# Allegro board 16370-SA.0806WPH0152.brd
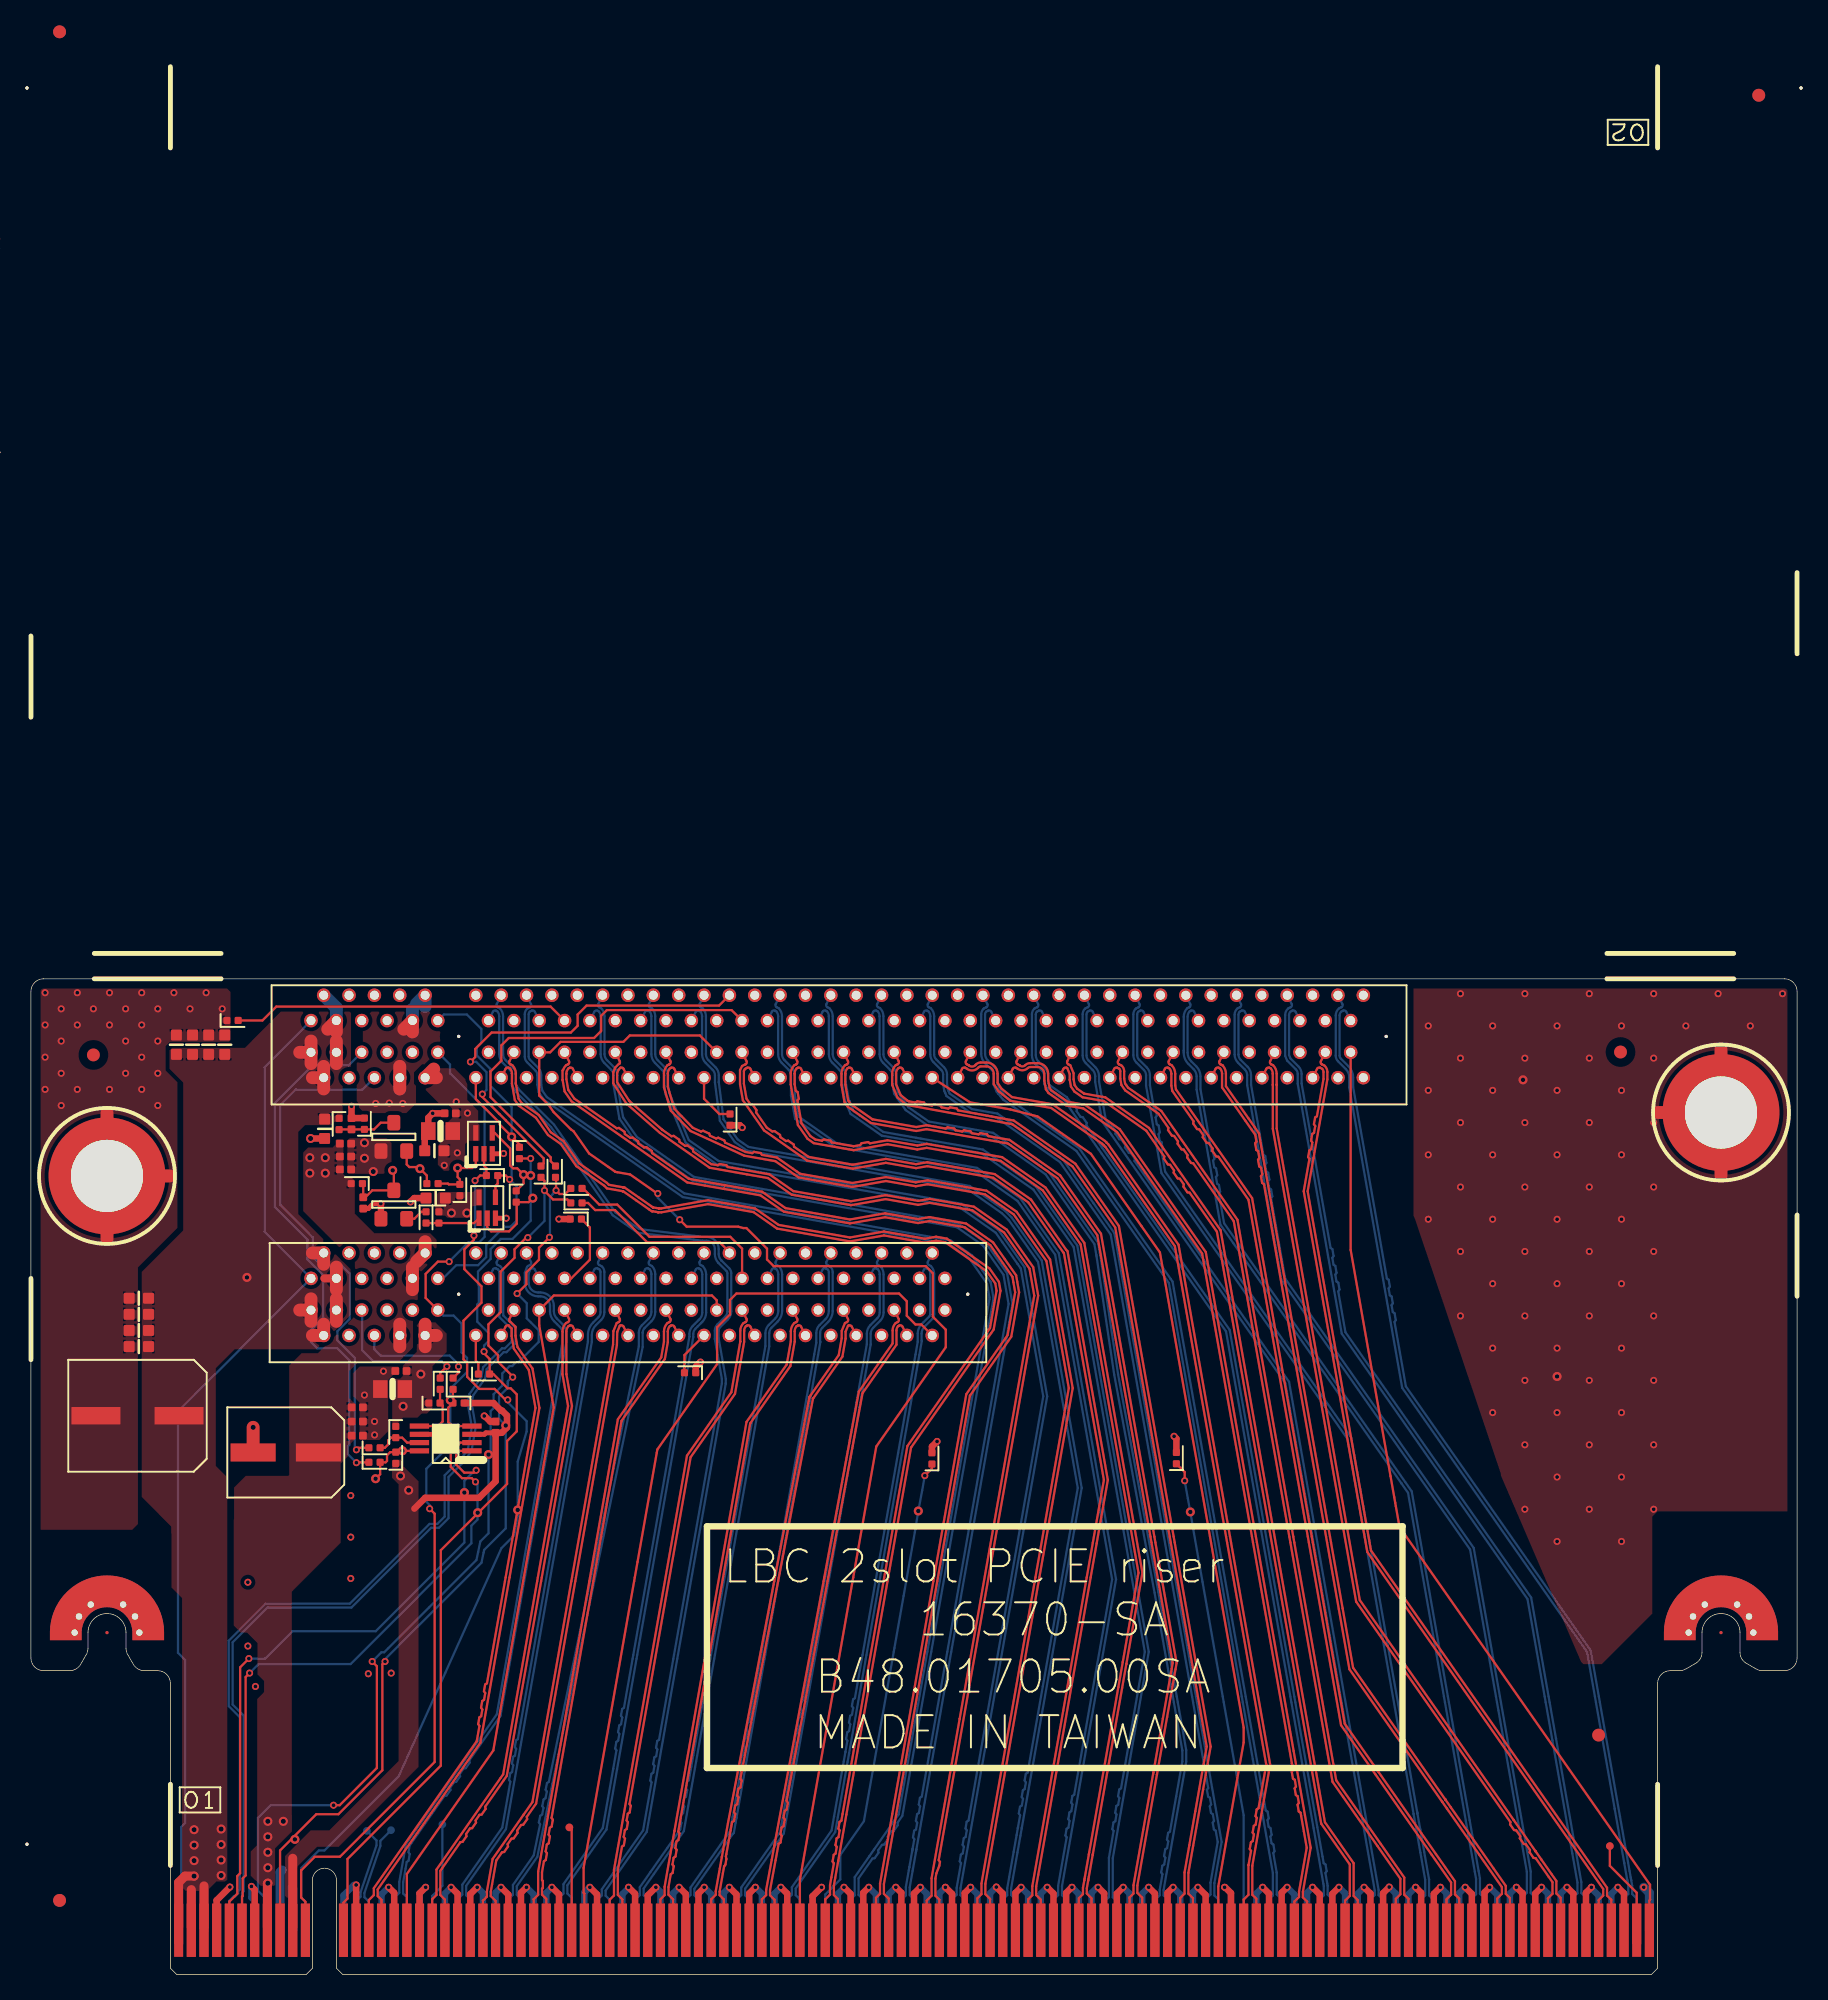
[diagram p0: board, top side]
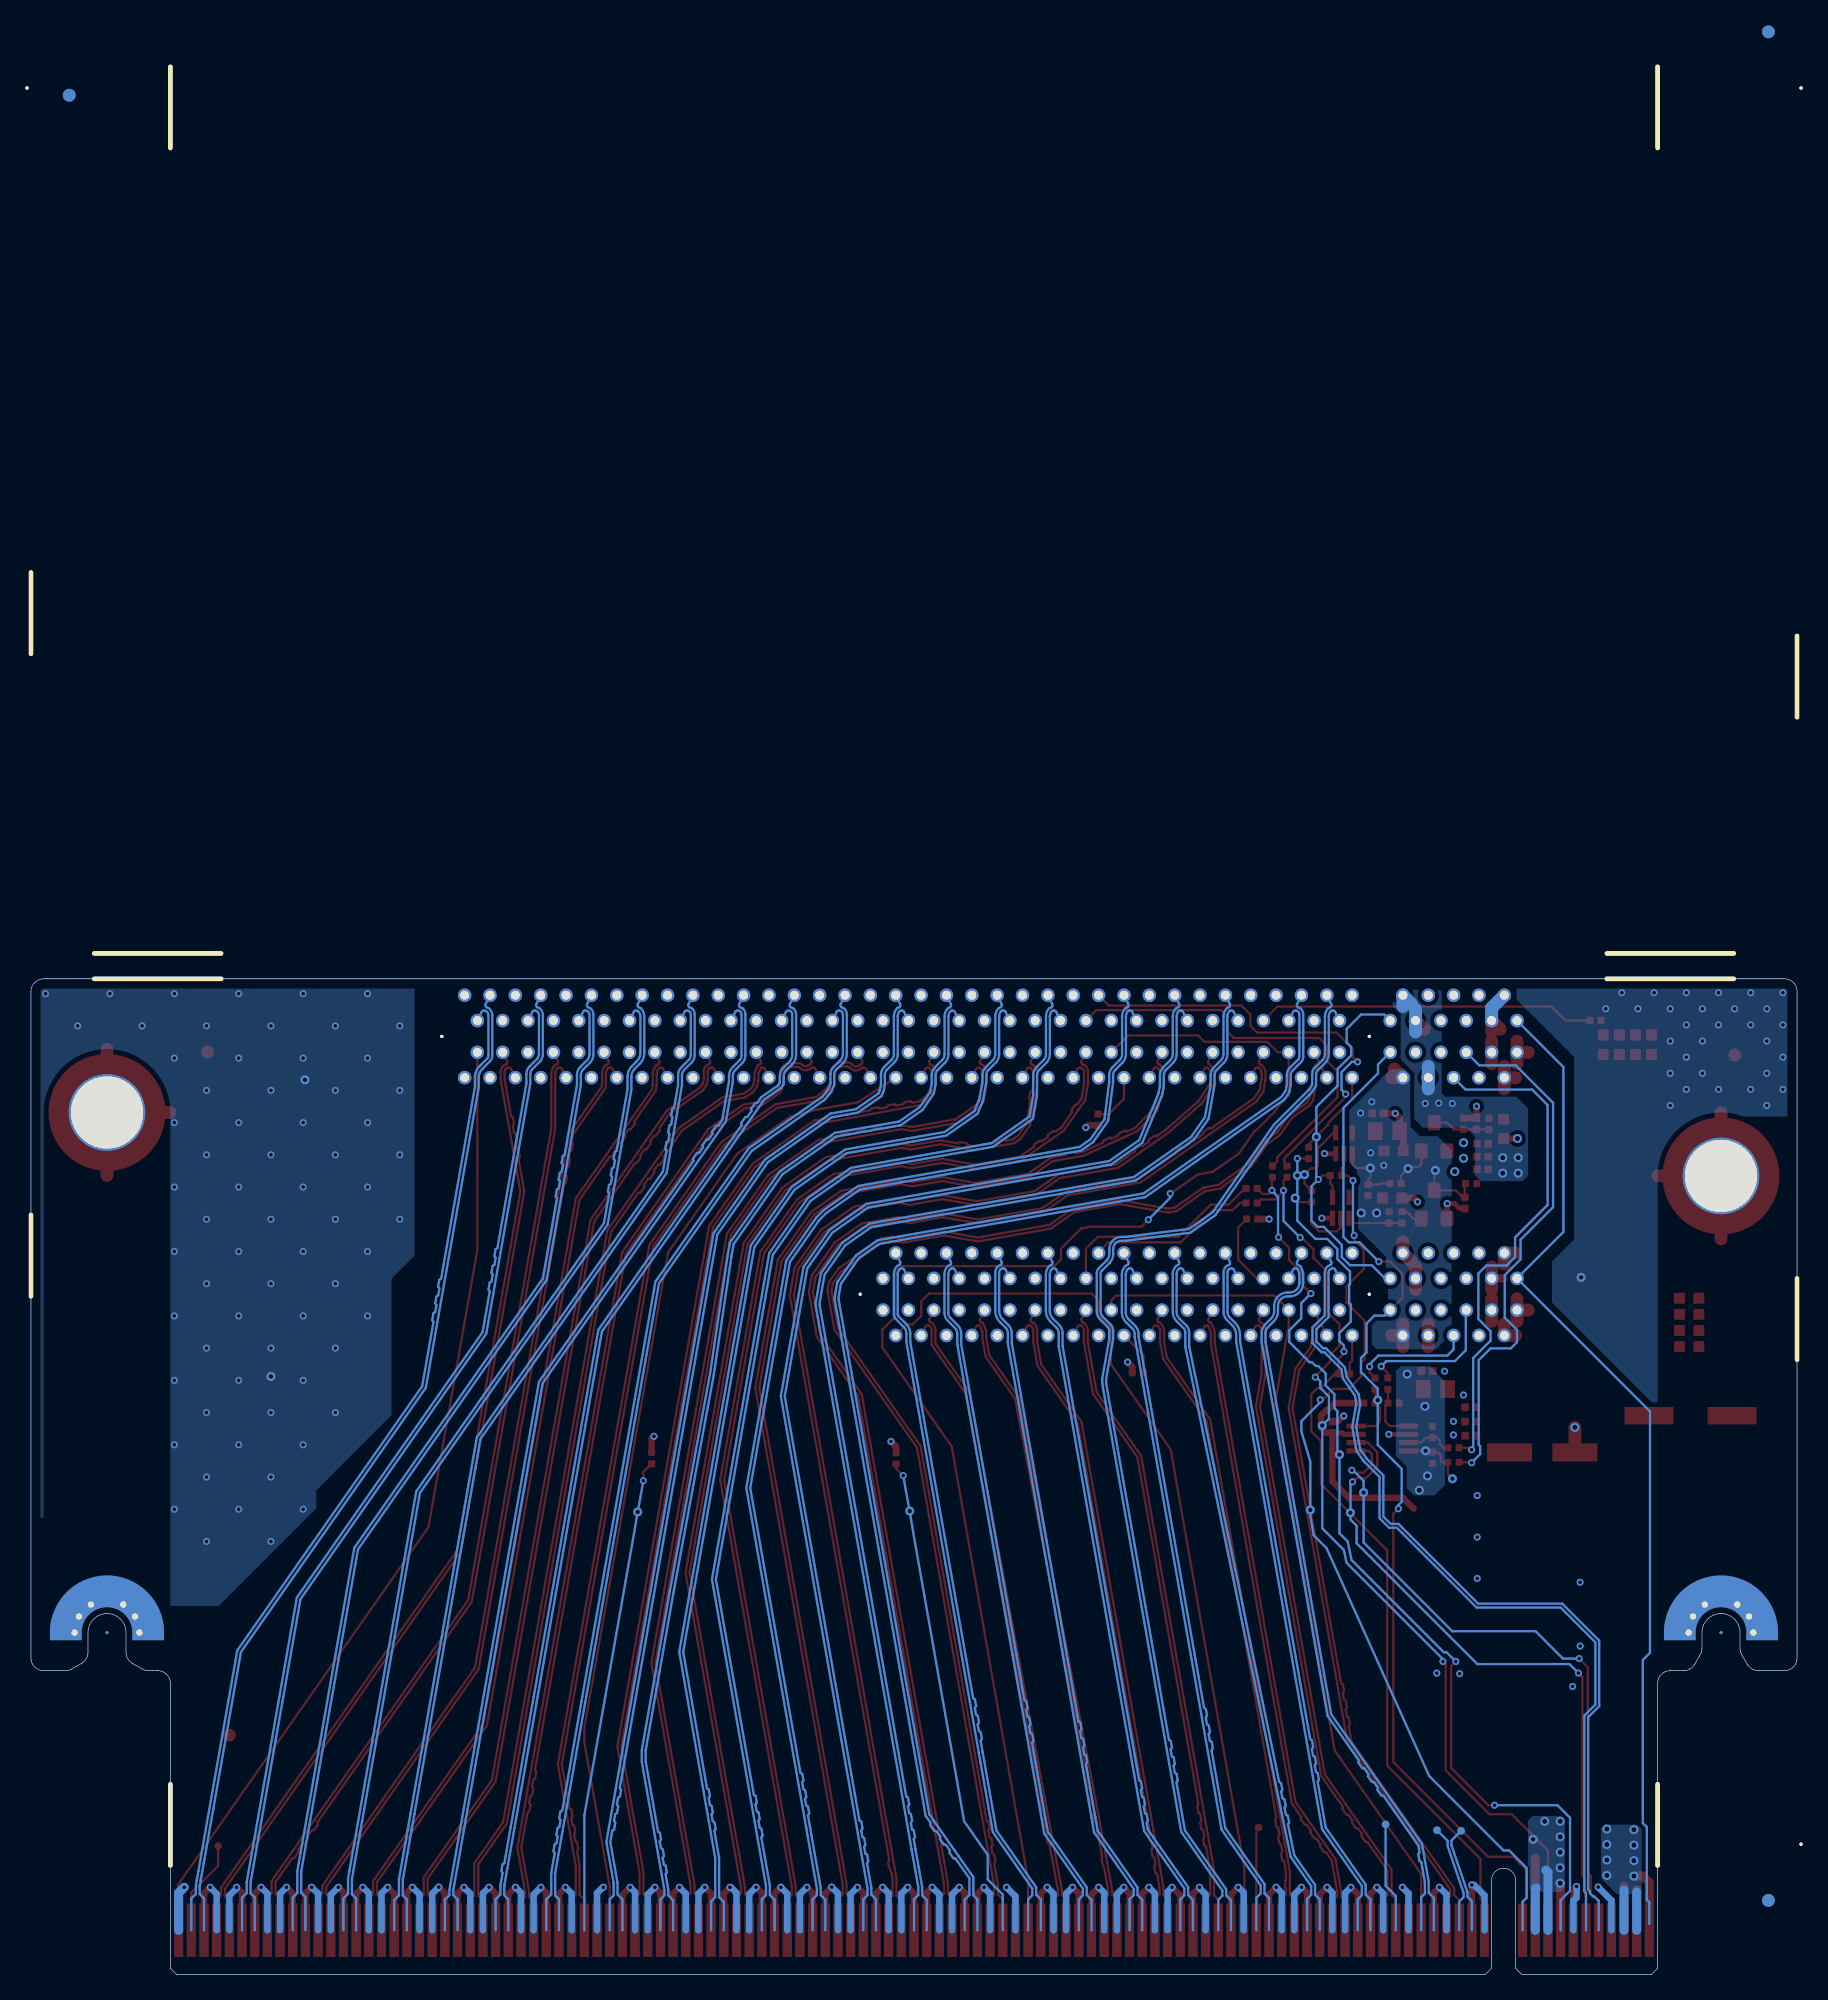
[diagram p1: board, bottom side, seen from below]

Outline 139.3 x 78.5 mm; copper layers: TOP, L2GND, L3GND, BOTTOM. Coordinates in mm from the lower left corner of the outline.
Outline path: 0,77.5 0,24.96 arc(0.29,24.25) 1,23.96 3.06,23.96 arc(3.56,24.09) 3.92,24.46 4.37,25.23 arc(4.47,25.47) 4.5,25.73 4.5,26.96 arc(6,28.46) 7.5,26.96 7.5,25.73 arc(7.53,25.47) 7.63,25.23 8.08,24.46 arc(8.44,24.09) 8.94,23.96 10,23.96 arc(10.71,23.67) 11,22.96 11,0.5 11.5,0 21.7,0 22.2,0.5 22.2,7.45 arc(23.15,8.4) 24.1,7.45 24.1,0.5 24.6,0 127.8,0 128.3,0.5 128.3,22.96 arc(128.59,23.67) 129.3,23.96 130.03,23.96 arc(130.29,23.99) 130.53,24.09 131.3,24.54 arc(131.67,24.9) 131.8,25.4 131.8,26.96 arc(133.3,28.46) 134.8,26.96 134.8,25.4 arc(134.93,24.9) 135.3,24.54 136.07,24.09 arc(136.31,23.99) 136.57,23.96 138.3,23.96 arc(139.01,24.25) 139.3,24.96 139.3,77.5 arc(139.01,78.21) 138.3,78.5 1,78.5 arc(0.29,78.21) 0,77.5 ; 3.2,62.96 arc(6,65.76) 8.8,62.96 arc(6,60.16) 3.2,62.96 ; 133.3,70.76 arc(136.1,67.96) 133.3,65.16 arc(130.5,67.96) 133.3,70.76

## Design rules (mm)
net group I2C: nets LAN_SMB_CLK LAN_SMB_DAT PCIE_SMCLK PCIE_SMCLK0 PCIE_SMCLK1 PCIE_SMDAT PCIE_SMDAT0 PCIE_SMDAT1 S0_PCIE_SMCLK S0_PCIE_SMDAT S0_SMB_CLK_A32 S0_SMB_DAT_A33 S1_PCIE_SMCLK S1_PCIE_SMDAT S1_SMB_CLK_A32 S1_SMB_DAT_A33
net group MISC: nets LAN_SMB_ALERT_N PCIE_CPRSNT_N PCIE_SLOT0_CPRSNT1_N PCIE_SLOT0_CPRSNT2_N PCIE_SLOT1_CPRSNT1_N PCIE_SLOT1_CPRSNT2_N PCIE_SLOT1_CPRSNT3_N PCIE_WAKE_N RSVD0 RSVD1 S0_SMB_ALERT_B12_N S1_SMB_ALERT_B12_N SLOT0_CONFIG SLOT0_ID_0 SLOT0_ID_1 SLOT1_CONFIG SLOT1_ID_0 SLOT1_ID_1
net group MISC_50_20_12: nets MB_PD_SLOT_PRSNT PCH_PLTRST_N PERST_N PERST_N_1 PERST_N_1_R PERST_O_1_R PERST_O_2_R RESET_IN RESET_O_1 RESET_O_2 RESET_P3V3_IN

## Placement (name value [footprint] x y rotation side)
C1  SCD1U25V3KX-GP  [C603H36]  11.48 73.31 180 top
C2  SCD1U25V3KX-GP  [C603H36]  12.75 73.31 180 top
C3  SCD1U25V3KX-GP  [C603H36]  14.02 73.31 180 top
C4  SCD1U25V3KX-GP  [C603H36]  15.29 73.31 180 top
C5  SCD1U16V2KX-3GP  [C402H22]  25.74 42.48 90 top
C6  SCD1U16V2KX-3GP  [C402H22]  25.74 43.6 90 top
C7  SCD1U16V2KX-3GP  [C402H22]  25.74 44.72 90 top
C8  SC10U6D3V5KX-4GP  [C805H58]  28.52 46.16 270 top
C9  SCD1U16V2KX-3GP  [C402H22]  29.18 47.58 270 top
C10  SCD1U25V3KX-GP  [C603H36]  8.51 53.32 270 top
C11  SCD1U25V3KX-GP  [C603H36]  8.51 52.05 270 top
C12  SCD1U25V3KX-GP  [C603H36]  8.51 50.78 270 top
C13  SCD1U25V3KX-GP  [C603H36]  8.51 49.51 270 top
C14  SCD1U16V2KX-3GP  [C402H22]  24.81 63.47 90 top
C15  SCD1U16V2KX-3GP  [C402H22]  24.81 64.49 90 top
C16  SCD1U16V2KX-3GP  [C402H22]  24.81 65.51 90 top
C17  SC10U6D3V5KX-4GP  [C805H58]  32.31 66.5 270 top
C18  SCD1U16V2KX-3GP  [C402H22]  33.07 67.89 270 top
C19  SCD01U16V2KX-3GP  [C402H22]  25.28 67.07 180 top
C20  SCD1U25V3KX-GP  [C603H36]  31.82 64.95 270 top
C21  SCD1U25V3KX-GP  [C603H36]  23.16 66.67 0 top
C22  SCD1U25V3KX-GP  [C603H36]  31.92 61.21 270 top
C23  SCD01U16V2KX-3GP  [C402H22]  26.21 60.83 0 top
C24  SCD1U16V2KX-3GP  [C402H22]  36.65 43.15 0 top
CN1  PCISLT98-79-GP  [G630H9811210TEU]  33.74 53.64 0 top
CN2  PCISLT164-33-GP  [2EG08227-D2W-DF]  33.74 73.96 0 top
GF1  GF-PCIE-230P-GP  [GF-PCIE-230P]  23.15 1.4 0 top
H1  STFT363B238R224H453-GP  [STFT363B238R224H453]  133.3 67.96 180 top
H2  STFT363B238R224H453-GP  [STFT363B238R224H453]  6 62.96 180 top
H3  GEN276X162R197X296-6-F-A-GP  [GEN276X162R197X296-6-F-A]  6 26.96 0 top
H4  GEN276X162R197X296-6-F-A-GP  [GEN276X162R197X296-6-F-A]  133.3 26.96 0 top
NOREF  -  []  -42 -27.95 0 top
NOREF#2  -  []  0 23.96 0 top
NOREF#3  *  [unnamed#2]  2.26 5.85 0 top
NOREF#4  -  [unnamed#2]  -0.31 10.28 0 top
NOREF#5  *  [unnamed#2]  136.28 148.15 0 top
NOREF#6  -  []  13.34 13.77 0 top
NOREF#7  *  [unnamed#2]  125.37 72.73 0 top
NOREF#8  -  [unnamed#2]  139.61 148.72 0 top
NOREF#9  -  []  -4 150.53 0 top
NOREF#10  -  []  0 23.96 0 top
NOREF#11  *  [unnamed#2]  4.93 72.5 0 top
NOREF#12  -  []  125.96 145.23 180 top
NOREF#13  -  []  0 23.96 0 top
NOREF#14  -  [unnamed#2]  -0.31 148.72 0 top
NOREF#15  *  [unnamed#2]  123.65 18.88 0 top
NOREF#16  *  [unnamed#2]  2.26 153.15 0 top
NOREF#17  *  [unnamed#2]  2.26 5.85 180 bottom
NOREF#18  *  [unnamed#2]  2.26 153.15 180 bottom
NOREF#19  *  [unnamed#2]  136.28 148.15 180 bottom
R1  8K2R2J-3-GP  [R402H16]  24.3 67.05 0 top
R2  3K3R2F-2-GP  [R402H16]  26.3 67.07 180 top
R3  0R2J-2-GP  [R402H16]  31.67 62.36 90 top
R4  0R2J-2-GP  [R402H16]  31.16 59.69 0 top
R5  0R2J-2-GP  [R402H16]  25.7 62.36 270 top
R6  0R2J-2-GP  [R402H16]  38.27 61.34 0 top
R7  100R2J-L-GP  [R402H15]  42.97 59.56 270 top
R8  100R2J-L-GP  [R402H15]  51.99 47.45 270 top
R9  100R2J-L-GP  [R402H15]  15.9 75.22 90 top
R10  100R2J-L-GP  [R402H15]  55.14 67.4 180 top
R13  4K7R2J-2-GP  [R402H16]  33.73 45.06 270 top
R14  4K7R2J-2-GP  [R402H16]  31.82 45.06 90 top
R15  4K7R2J-2-GP  [R402H16]  28.78 42.77 0 top
R16  4K7R2J-2-GP  [R402H16]  28.78 40.74 180 top
R17  4K7R2J-2-GP  [R402H16]  33.83 61.85 180 top
R19  0R2J-2-GP  [R402H16]  36.37 62.99 270 top
R20  4K7R2J-2-GP  [R402H16]  32.18 59.69 0 top
R33  1KR2J-1-GP  [R402H16]  71.07 40.69 180 top
R35  1KR2J-1-GP  [R402H16]  90.34 40.71 180 top
RE1  0R2J-2-GP  [R402H16]  32.28 46.58 0 top
RE2  0R2J-2-GP  [R402H16]  43.02 60.83 90 top
RE3  0R2J-2-GP  [R402H16]  43.02 61.97 90 top
RE4  0R2J-2-GP  [R402H16]  35.73 47.34 90 top
RE5  0R2J-2-GP  [R402H16]  40.23 63.3 180 top
RE6  0R2J-2-GP  [R402H16]  41.37 63.3 180 top
RE7  0R2J-2-GP  [R402H16]  33.3 46.58 0 top
RE8  0R2J-2-GP  [R402H16]  38.53 64.77 0 top
RE9  0R2J-2-GP  [R402H16]  27.1 41.53 90 top
RE10  0R2J-2-GP  [R402H16]  27.1 40.38 90 top
TC3  SE270U16VM-2-GP  [SE391427H276]  8.4 44.06 270 top
TC4  SE220U6D3VM-8GP  [SE331721H237]  20.1 41.16 270 top
TP1  -  [TPAD24]  26.5 11.33 180 bottom
TP2  -  [TPAD24]  28.4 11.39 180 bottom
TP3  -  [TPAD24]  124.53 10.13 0 top
TP6  -  [TPAD24]  42.47 11.61 0 top
TP7  -  [TPAD24]  32.45 11.84 180 bottom
U1  TPS3809K33-2-GP  [SOT-23-1H58]  28.62 66.04 0 top
U2  TPS3809K33-2-GP  [SOT-23-1H58]  28.62 60.7 0 top
U8  SNLVC1G08DCKRG4-GP  [SC70-5H44]  35.73 65.53 180 top
U9  SNLVC1G08DCKRG4-GP  [SC70-5H44]  35.99 60.45 180 top
U10  PCA9540BDP-T-GP  [SSOIC8-2H44]  32.71 42.26 90 top

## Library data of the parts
C1-C4 C10-C13 C20-C22 = C603H36: tolerance: 78.10422.2BL
C5-C7 C9 C14-C16 C18 C24 = C402H22: tolerance: 78.10421.2FL
C8 C17 = C805H58: tolerance: 78.10620.21L
C19 C23 = C402H22: tolerance: 78.10321.2FL
CN1 = G630H9811210TEU: tolerance: 020.50107.0098
CN2 = 2EG08227-D2W-DF: tolerance: 20.50449.164
GF1 = GF-PCIE-230P: tolerance: ZZ.GF001.711; alternate symbols: (TOP:GF-PCIE-230P)
H1 H2 = STFT363B238R224H453: tolerance: 086.2AT24.04R6
H3 H4 = GEN276X162R197X296-6-F-A: tolerance: ZZ.SCREW.511
R1 = R402H16: tolerance: 63.82234.1DL
R2 = R402H16: tolerance: 64.33015.6DL
R3-R6 R19 RE1-RE10 = R402H16: tolerance: 63.R0034.1DL
R7-R10 = R402H15: tolerance: 63.10134.L0L
R13-R17 R20 = R402H16: tolerance: 63.47234.1DL
R33 R35 = R402H16: tolerance: 63.10234.1DL
TC3 = SE391427H276: tolerance: 77.52771.01L
TC4 = SE331721H237: tolerance: 79.22710.E0L
TP1-TP3 TP6 TP7 = TPAD24: tolerance: ZZ.PAD24.001
U1 U2 = SOT-23-1H58: tolerance: 74.03809.07B
U8 U9 = SC70-5H44: tolerance: 73.01G08.DHG
U10 = SSOIC8-2H44: tolerance: 71.09540.A0W

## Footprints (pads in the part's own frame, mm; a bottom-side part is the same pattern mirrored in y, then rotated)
2EG08227-D2W-DF
  round 0.254 hole 2.362 unplated: (0,0) (73.15,0)
  round 1.067 hole 0.711: A1(-11.65,1.25) A2(-10.65,3.25) A3(-9.65,1.25) A4(-8.65,3.25) A5(-7.65,1.25) A6(-6.65,3.25) A7(-5.65,1.25) A8(-4.65,3.25) A9(-3.65,1.25) A10(-2.65,3.25) A11(-1.65,1.25) A12(1.35,3.25) A13(2.35,1.25) A14(3.35,3.25) A15(4.35,1.25) A16(5.35,3.25) A17(6.35,1.25) A18(7.35,3.25) A19(8.35,1.25) A20(9.35,3.25) A21(10.35,1.25) A22(11.35,3.25) A23(12.35,1.25) A24(13.35,3.25) A25(14.35,1.25) A26(15.35,3.25) A27(16.35,1.25) A28(17.35,3.25) A29(18.35,1.25) A30(19.35,3.25) A31(20.35,1.25) A32(21.35,3.25) A33(22.35,1.25) A34(23.35,3.25) A35(24.35,1.25) A36(25.35,3.25) A37(26.35,1.25) A38(27.35,3.25) A39(28.35,1.25) A40(29.35,3.25) A41(30.35,1.25) A42(31.35,3.25) A43(32.35,1.25) A44(33.35,3.25) A45(34.35,1.25) A46(35.35,3.25) A47(36.35,1.25) A48(37.35,3.25) A49(38.35,1.25) A50(39.35,3.25) A51(40.35,1.25) A52(41.35,3.25) A53(42.35,1.25) A54(43.35,3.25) A55(44.35,1.25) A56(45.35,3.25) A57(46.35,1.25) A58(47.35,3.25) A59(48.35,1.25) A60(49.35,3.25) A61(50.35,1.25) A62(51.35,3.25) A63(52.35,1.25) A64(53.35,3.25) A65(54.35,1.25) A66(55.35,3.25) A67(56.35,1.25) A68(57.35,3.25) A69(58.35,1.25) A70(59.35,3.25) A71(60.35,1.25) A72(61.35,3.25) A73(62.35,1.25) A74(63.35,3.25) A75(64.35,1.25) A76(65.35,3.25) A77(66.35,1.25) A78(67.35,3.25) A79(68.35,1.25) A80(69.35,3.25) A81(70.35,1.25) A82(71.35,3.25) B1(-11.65,-1.25) B2(-10.65,-3.25) B3(-9.65,-1.25) B4(-8.65,-3.25) B5(-7.65,-1.25) B6(-6.65,-3.25) B7(-5.65,-1.25) B8(-4.65,-3.25) B9(-3.65,-1.25) B10(-2.65,-3.25) B11(-1.65,-1.25) B12(1.35,-3.25) B13(2.35,-1.25) B14(3.35,-3.25) B15(4.35,-1.25) B16(5.35,-3.25) B17(6.35,-1.25) B18(7.35,-3.25) B19(8.35,-1.25) B20(9.35,-3.25) B21(10.35,-1.25) B22(11.35,-3.25) B23(12.35,-1.25) B24(13.35,-3.25) B25(14.35,-1.25) B26(15.35,-3.25) B27(16.35,-1.25) B28(17.35,-3.25) B29(18.35,-1.25) B30(19.35,-3.25) B31(20.35,-1.25) B32(21.35,-3.25) B33(22.35,-1.25) B34(23.35,-3.25) B35(24.35,-1.25) B36(25.35,-3.25) B37(26.35,-1.25) B38(27.35,-3.25) B39(28.35,-1.25) B40(29.35,-3.25) B41(30.35,-1.25) B42(31.35,-3.25) B43(32.35,-1.25) B44(33.35,-3.25) B45(34.35,-1.25) B46(35.35,-3.25) B47(36.35,-1.25) B48(37.35,-3.25) B49(38.35,-1.25) B50(39.35,-3.25) B51(40.35,-1.25) B52(41.35,-3.25) B53(42.35,-1.25) B54(43.35,-3.25) B55(44.35,-1.25) B56(45.35,-3.25) B57(46.35,-1.25) B58(47.35,-3.25) B59(48.35,-1.25) B60(49.35,-3.25) B61(50.35,-1.25) B62(51.35,-3.25) B63(52.35,-1.25) B64(53.35,-3.25) B65(54.35,-1.25) B66(55.35,-3.25) B67(56.35,-1.25) B68(57.35,-3.25) B69(58.35,-1.25) B70(59.35,-3.25) B71(60.35,-1.25) B72(61.35,-3.25) B73(62.35,-1.25) B74(63.35,-3.25) B75(64.35,-1.25) B76(65.35,-3.25) B77(66.35,-1.25) B78(67.35,-3.25) B79(68.35,-1.25) B80(69.35,-3.25) B81(70.35,-1.25) B82(71.35,-3.25)
C402H22
  custom 0.152x0.152 smd: 1(0,0.445) 2(0,-0.445)
C603H36
  custom 0.216x0.216 smd: 1(0,0.762) 2(0,-0.762)
C805H58
  rect 1.397x1.143 smd: 1(0,0.965) 2(0,-0.965)
G630H9811210TEU
  round 0.254 hole 2.362 unplated: (0,0) (40.15,0)
  round 1.067 hole 0.711: A1(-11.65,1.25) A2(-10.65,3.25) A3(-9.65,1.25) A4(-8.65,3.25) A5(-7.65,1.25) A6(-6.65,3.25) A7(-5.65,1.25) A8(-4.65,3.25) A9(-3.65,1.25) A10(-2.65,3.25) A11(-1.65,1.25) A12(1.35,3.25) A13(2.35,1.25) A14(3.35,3.25) A15(4.35,1.25) A16(5.35,3.25) A17(6.35,1.25) A18(7.35,3.25) A19(8.35,1.25) A20(9.35,3.25) A21(10.35,1.25) A22(11.35,3.25) A23(12.35,1.25) A24(13.35,3.25) A25(14.35,1.25) A26(15.35,3.25) A27(16.35,1.25) A28(17.35,3.25) A29(18.35,1.25) A30(19.35,3.25) A31(20.35,1.25) A32(21.35,3.25) A33(22.35,1.25) A34(23.35,3.25) A35(24.35,1.25) A36(25.35,3.25) A37(26.35,1.25) A38(27.35,3.25) A39(28.35,1.25) A40(29.35,3.25) A41(30.35,1.25) A42(31.35,3.25) A43(32.35,1.25) A44(33.35,3.25) A45(34.35,1.25) A46(35.35,3.25) A47(36.35,1.25) A48(37.35,3.25) A49(38.35,1.25) B1(-11.65,-1.25) B2(-10.65,-3.25) B3(-9.65,-1.25) B4(-8.65,-3.25) B5(-7.65,-1.25) B6(-6.65,-3.25) B7(-5.65,-1.25) B8(-4.65,-3.25) B9(-3.65,-1.25) B10(-2.65,-3.25) B11(-1.65,-1.25) B12(1.35,-3.25) B13(2.35,-1.25) B14(3.35,-3.25) B15(4.35,-1.25) B16(5.35,-3.25) B17(6.35,-1.25) B18(7.35,-3.25) B19(8.35,-1.25) B20(9.35,-3.25) B21(10.35,-1.25) B22(11.35,-3.25) B23(12.35,-1.25) B24(13.35,-3.25) B25(14.35,-1.25) B26(15.35,-3.25) B27(16.35,-1.25) B28(17.35,-3.25) B29(18.35,-1.25) B30(19.35,-3.25) B31(20.35,-1.25) B32(21.35,-3.25) B33(22.35,-1.25) B34(23.35,-3.25) B35(24.35,-1.25) B36(25.35,-3.25) B37(26.35,-1.25) B38(27.35,-3.25) B39(28.35,-1.25) B40(29.35,-3.25) B41(30.35,-1.25) B42(31.35,-3.25) B43(32.35,-1.25) B44(33.35,-3.25) B45(34.35,-1.25) B46(35.35,-3.25) B47(36.35,-1.25) B48(37.35,-3.25) B49(38.35,-1.25)
GEN276X162R197X296-6-F-A
  round 0.254 hole 0.025 unplated: (0,0)
  round 0.864 hole 0.508: 1(2.55,0) 2(2.21,1.27) 3(1.27,2.21) 4(-1.28,2.21) 5(-2.21,1.27) 6(-2.55,0)
GF-PCIE-230P
  rect 0.711x3.2 smd: A1(-11.5,2.591) B114(103.5,2.591)
  rect 0.711x4.191 smd: A2(-10.5,2.095) A3(-9.5,2.095) A4(-8.5,2.095) A5(-7.5,2.095) A6(-6.5,2.095) A7(-5.5,2.095) A8(-4.5,2.095) A9(-3.5,2.095) A10(-2.5,2.095) A11(-1.5,2.095) A12(1.5,2.095) A13(2.5,2.095) A14(3.5,2.095) A15(4.5,2.095) A16(5.5,2.095) A17(6.5,2.095) A18(7.5,2.095) A19(8.5,2.095) A20(9.5,2.095) A21(10.5,2.095) A22(11.5,2.095) A23(12.5,2.095) A24(13.5,2.095) A25(14.5,2.095) A26(15.5,2.095) A27(16.5,2.095) A28(17.5,2.095) A29(18.5,2.095) A30(19.5,2.095) A31(20.5,2.095) A32(21.5,2.095) A33(22.5,2.095) A34(23.5,2.095) A35(24.5,2.095) A36(25.5,2.095) A37(26.5,2.095) A38(27.5,2.095) A39(28.5,2.095) A40(29.5,2.095) A41(30.5,2.095) A42(31.5,2.095) A43(32.5,2.095) A44(33.5,2.095) A45(34.5,2.095) A46(35.5,2.095) A47(36.5,2.095) A48(37.5,2.095) A49(38.5,2.095) A50(39.5,2.095) A51(40.5,2.095) A52(41.5,2.095) A53(42.5,2.095) A54(43.5,2.095) A55(44.5,2.095) A56(45.5,2.095) A57(46.5,2.095) A58(47.5,2.095) A59(48.5,2.095) A60(49.5,2.095) A61(50.5,2.095) A62(51.5,2.095) A63(52.5,2.095) A64(53.5,2.095) A65(54.5,2.095) A66(55.5,2.095) A67(56.5,2.095) A68(57.5,2.095) A69(58.5,2.095) A70(59.5,2.095) A71(60.5,2.095) A72(61.5,2.095) A73(62.5,2.095) A74(63.5,2.095) A75(64.5,2.095) A76(65.5,2.095) A77(66.5,2.095) A78(67.5,2.095) A79(68.5,2.095) A80(69.5,2.095) A81(70.5,2.095) A82(71.5,2.095) A83(72.5,2.095) A84(73.5,2.095) A85(74.5,2.095) A86(75.5,2.095) A87(76.5,2.095) A88(77.5,2.095) A89(78.5,2.095) A90(79.5,2.095) A91(80.5,2.095) A92(81.5,2.095) A93(82.5,2.095) A94(83.5,2.095) A95(84.5,2.095) A96(85.5,2.095) A97(86.5,2.095) A98(87.5,2.095) A99(88.5,2.095) A100(89.5,2.095) A101(90.5,2.095) A102(91.5,2.095) A103(92.5,2.095) A104(93.5,2.095) A105(94.5,2.095) A106(95.5,2.095) A107(96.5,2.095) A108(97.5,2.095) A109(98.5,2.095) A110(99.5,2.095) A111(100.5,2.095) A112(101.5,2.095) A113(102.5,2.095) A114(103.5,2.095) A115(104.5,2.095) B1(-11.5,2.349) B2(-10.5,2.349) B3(-9.5,2.349) B4(-8.5,2.349) B5(-7.5,2.349) B6(-6.5,2.349) B7(-5.5,2.349) B8(-4.5,2.349) B9(-3.5,2.349) B10(-2.5,2.349) B11(-1.5,2.349) B12(1.5,2.349) B13(2.5,2.349) B14(3.5,2.349) B15(4.5,2.349) B16(5.5,2.349) B17(6.5,2.349) B18(7.5,2.349) B19(8.5,2.349) B20(9.5,2.349) B21(10.5,2.349) B22(11.5,2.349) B23(12.5,2.349) B24(13.5,2.349) B25(14.5,2.349) B26(15.5,2.349) B27(16.5,2.349) B28(17.5,2.349) B29(18.5,2.349) B30(19.5,2.349) B31(20.5,2.349) B32(21.5,2.349) B33(22.5,2.349) B34(23.5,2.349) B35(24.5,2.349) B36(25.5,2.349) B37(26.5,2.349) B38(27.5,2.349) B39(28.5,2.349) B40(29.5,2.349) B41(30.5,2.349) B42(31.5,2.349) B43(32.5,2.349) B44(33.5,2.349) B45(34.5,2.349) B46(35.5,2.349) B47(36.5,2.349) B48(37.5,2.349) B49(38.5,2.349) B50(39.5,2.349) B51(40.5,2.349) B52(41.5,2.349) B53(42.5,2.349) B54(43.5,2.349) B55(44.5,2.349) B56(45.5,2.349) B57(46.5,2.349) B58(47.5,2.349) B59(48.5,2.349) B60(49.5,2.349) B61(50.5,2.349) B62(51.5,2.349) B63(52.5,2.349) B64(53.5,2.349) B65(54.5,2.349) B66(55.5,2.349) B67(56.5,2.349) B68(57.5,2.349) B69(58.5,2.349) B70(59.5,2.349) B71(60.5,2.349) B72(61.5,2.349) B73(62.5,2.349) B74(63.5,2.349) B75(64.5,2.349) B76(65.5,2.349) B77(66.5,2.349) B78(67.5,2.349) B79(68.5,2.349) B80(69.5,2.349) B81(70.5,2.349) B82(71.5,2.349) B83(72.5,2.349) B84(73.5,2.349) B85(74.5,2.349) B86(75.5,2.349) B87(76.5,2.349) B88(77.5,2.349) B89(78.5,2.349) B90(79.5,2.349) B91(80.5,2.349) B92(81.5,2.349) B93(82.5,2.349) B94(83.5,2.349) B95(84.5,2.349) B96(85.5,2.349) B97(86.5,2.349) B98(87.5,2.349) B99(88.5,2.349) B100(89.5,2.349) B101(90.5,2.349) B102(91.5,2.349) B103(92.5,2.349) B104(93.5,2.349) B105(94.5,2.349) B106(95.5,2.349) B107(96.5,2.349) B108(97.5,2.349) B109(98.5,2.349) B110(99.5,2.349) B111(100.5,2.349) B112(101.5,2.349) B113(102.5,2.349) B115(104.5,2.349)
R402H15
  custom 0.14x0.14 smd: 1(0,0.445) 2(0,-0.445)
R402H16
  custom 0.14x0.14 smd: 1(0,0.445) 2(0,-0.445)
SC70-5H44
  rect 0.406x1.219 smd: 1(0.65,0.826) 2(0,0.826) 3(-0.65,0.826) 4(-0.65,-0.826) 5(0.65,-0.826)
SE331721H237
  rect 1.422x3.556 smd: 1(0,2.574) 2(0,-2.574)
SE391427H276
  rect 1.372x3.861 smd: 1(0,3.276) 2(0,-3.276)
SOT-23-1H58
  custom 0.254x0.254 smd: 1(-1.016,-1.118) 2(1.016,-1.118) 3(0,1.118)
SSOIC8-2H44
  rect 0.406x1.524 smd: 1(-0.975,-2.07) 2(-0.325,-2.07) 3(0.325,-2.07) 4(0.975,-2.07) 5(0.975,2.07) 6(0.325,2.07) 7(-0.325,2.07) 8(-0.975,2.07)
STFT363B238R224H453
  round 9.22 hole 5.69: 1(0,0)
TPAD24
  round 0.61 smd: 1(0,0)
unnamed#2
  round 1.016 smd: (0,0)

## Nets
GND: C1.2 C2.2 C3.2 C4.2 C5.2 C6.2 C7.2 C8.2 C9.2 C10.2 C11.2 C12.2 C13.2 C14.2 C15.2 C16.2 C17.2 C18.2 C19.2 C20.2 C21.2 C22.2 C23.2 C24.1 CN1.A4 CN1.A12 CN1.A15 CN1.A18 CN1.A20 CN1.A23 CN1.A24 CN1.A27 CN1.A28 CN1.A31 CN1.A34 CN1.A37 CN1.A38 CN1.A41 CN1.A42 CN1.A45 CN1.A46 CN1.A49 CN1.B4 CN1.B7 CN1.B13 CN1.B16 CN1.B18 CN1.B21 CN1.B22 CN1.B25 CN1.B26 CN1.B29 CN1.B32 CN1.B35 CN1.B36 CN1.B39 CN1.B40 CN1.B43 CN1.B44 CN1.B47 CN1.B49 CN2.A4 CN2.A12 CN2.A15 CN2.A18 CN2.A20 CN2.A23 CN2.A24 CN2.A27 CN2.A28 CN2.A31 CN2.A34 CN2.A37 CN2.A38 CN2.A41 CN2.A42 CN2.A45 CN2.A46 CN2.A49 CN2.A51 CN2.A54 CN2.A55 CN2.A58 CN2.A59 CN2.A62 CN2.A63 CN2.A66 CN2.A67 CN2.A70 CN2.A71 CN2.A74 CN2.A75 CN2.A78 CN2.A79 CN2.A82 CN2.B4 CN2.B7 CN2.B13 CN2.B16 CN2.B18 CN2.B21 CN2.B22 CN2.B25 CN2.B26 CN2.B29 CN2.B32 CN2.B35 CN2.B36 CN2.B39 CN2.B40 CN2.B43 CN2.B44 CN2.B47 CN2.B49 CN2.B52 CN2.B53 CN2.B56 CN2.B57 CN2.B60 CN2.B61 CN2.B64 CN2.B65 CN2.B68 CN2.B69 CN2.B72 CN2.B73 CN2.B76 CN2.B77 CN2.B80 GF1.A4 GF1.A7 GF1.A12 GF1.A15 GF1.A18 GF1.A20 GF1.A23 GF1.A24 GF1.A27 GF1.A28 GF1.A31 GF1.A34 GF1.A37 GF1.A38 GF1.A41 GF1.A42 GF1.A45 GF1.A46 GF1.A49 GF1.A51 GF1.A54 GF1.A55 GF1.A58 GF1.A59 GF1.A62 GF1.A63 GF1.A66 GF1.A67 GF1.A70 GF1.A71 GF1.A74 GF1.A75 GF1.A78 GF1.A79 GF1.A82 GF1.A84 GF1.A87 GF1.A88 GF1.A91 GF1.A92 GF1.A95 GF1.A96 GF1.A99 GF1.A100 GF1.A103 GF1.A104 GF1.A107 GF1.A108 GF1.A111 GF1.A112 GF1.A115 GF1.B4 GF1.B7 GF1.B13 GF1.B16 GF1.B18 GF1.B21 GF1.B22 GF1.B25 GF1.B26 GF1.B29 GF1.B32 GF1.B35 GF1.B36 GF1.B39 GF1.B40 GF1.B43 GF1.B44 GF1.B47 GF1.B49 GF1.B52 GF1.B53 GF1.B56 GF1.B57 GF1.B60 GF1.B61 GF1.B64 GF1.B65 GF1.B68 GF1.B69 GF1.B72 GF1.B73 GF1.B76 GF1.B77 GF1.B80 GF1.B82 GF1.B85 GF1.B86 GF1.B89 GF1.B90 GF1.B93 GF1.B94 GF1.B97 GF1.B98 GF1.B101 GF1.B102 GF1.B105 GF1.B106 GF1.B109 GF1.B110 GF1.B113 H1.1 H2.1 H3.1 H3.2 H3.3 H3.4 H3.5 H3.6 H4.1 H4.2 H4.3 H4.4 H4.5 H4.6 R2.2 R7.2 R8.1 R9.1 R10.1 R33.2 R35.2 TC3.2 TC4.2 U1.1 U2.1 U8.3 U9.3 U10.6
P3V3: C5.1 C6.1 C7.1 C14.1 C15.1 C16.1 CN1.A9 CN1.A10 CN1.B8 CN2.A9 CN2.A10 CN2.B8 GF1.A9 GF1.A10 GF1.B8 R5.2 TC4.1
P3V3_AUX: C8.1 C9.1 C17.1 C18.1 C20.1 C22.1 C24.2 CN1.B10 CN2.B10 GF1.B10 R13.1 R14.1 R15.1 R16.1 R17.1 R20.1 U8.5 U9.5 U10.3
P12V: C1.1 C2.1 C3.1 C4.1 C10.1 C11.1 C12.1 C13.1 C21.1 CN1.A2 CN1.A3 CN1.B1 CN1.B2 CN1.B3 CN2.A2 CN2.A3 CN2.B1 CN2.B2 CN2.B3 GF1.A2 GF1.A3 GF1.B1 GF1.B2 GF1.B3 R1.1 TC3.1
CLK100_PCIE_SLOT0_N: CN1.A14 GF1.A6
CLK100_PCIE_SLOT0_P: CN1.A13 GF1.A5
CLK100_PCIE_SLOT1_N: CN2.A14 GF1.A33
CLK100_PCIE_SLOT1_P: CN2.A13 GF1.A32
CLK100_PCIE_SLOT_N: GF1.A14 TP2.1
CLK100_PCIE_SLOT_P: GF1.A13 TP1.1
LAN_SMB_ALERT_N: GF1.B12 RE4.2 RE8.2
LAN_SMB_CLK: GF1.B9 RE2.1 RE5.1
LAN_SMB_DAT: GF1.A8 RE3.1 RE6.1
MB_PD_SLOT_PRSNT: CN1.A1 CN2.A1 GF1.A1
PCH_PLTRST_N: GF1.A11 R19.2 U8.2
PCIE_CPRSNT_N: GF1.B114 TP3.1
PCIE_SLOT0_CPRSNT1_N: CN1.B17 CN1.B31 GF1.B17
PCIE_SLOT0_CPRSNT2_N: CN1.B48 GF1.B31
PCIE_SLOT0_RXN0: CN1.A17 GF1.A17
PCIE_SLOT0_RXN1: CN1.A22 GF1.A22
PCIE_SLOT0_RXN2: CN1.A26 GF1.A26
PCIE_SLOT0_RXN3: CN1.A30 GF1.A30
PCIE_SLOT0_RXN4: CN1.A36 GF1.A36
PCIE_SLOT0_RXN5: CN1.A40 GF1.A40
PCIE_SLOT0_RXN6: CN1.A44 GF1.A44
PCIE_SLOT0_RXN7: CN1.A48 GF1.A48
PCIE_SLOT0_RXP0: CN1.A16 GF1.A16
PCIE_SLOT0_RXP1: CN1.A21 GF1.A21
PCIE_SLOT0_RXP2: CN1.A25 GF1.A25
PCIE_SLOT0_RXP3: CN1.A29 GF1.A29
PCIE_SLOT0_RXP4: CN1.A35 GF1.A35
PCIE_SLOT0_RXP5: CN1.A39 GF1.A39
PCIE_SLOT0_RXP6: CN1.A43 GF1.A43
PCIE_SLOT0_RXP7: CN1.A47 GF1.A47
PCIE_SLOT0_TXN0: CN1.B15 GF1.B15
PCIE_SLOT0_TXN1: CN1.B20 GF1.B20
PCIE_SLOT0_TXN2: CN1.B24 GF1.B24
PCIE_SLOT0_TXN3: CN1.B28 GF1.B28
PCIE_SLOT0_TXN4: CN1.B34 GF1.B34
PCIE_SLOT0_TXN5: CN1.B38 GF1.B38
PCIE_SLOT0_TXN6: CN1.B42 GF1.B42
PCIE_SLOT0_TXN7: CN1.B46 GF1.B46
PCIE_SLOT0_TXP0: CN1.B14 GF1.B14
PCIE_SLOT0_TXP1: CN1.B19 GF1.B19
PCIE_SLOT0_TXP2: CN1.B23 GF1.B23
PCIE_SLOT0_TXP3: CN1.B27 GF1.B27
PCIE_SLOT0_TXP4: CN1.B33 GF1.B33
PCIE_SLOT0_TXP5: CN1.B37 GF1.B37
PCIE_SLOT0_TXP6: CN1.B41 GF1.B41
PCIE_SLOT0_TXP7: CN1.B45 GF1.B45
PCIE_SLOT1_CPRSNT1_N: CN2.B17 CN2.B31 GF1.B48
PCIE_SLOT1_CPRSNT2_N: CN2.B48 GF1.B81
PCIE_SLOT1_CPRSNT3_N: CN2.B81 GF1.B115
PCIE_SLOT1_RXN0: CN2.A17 GF1.A53
PCIE_SLOT1_RXN1: CN2.A22 GF1.A57
PCIE_SLOT1_RXN2: CN2.A26 GF1.A61
PCIE_SLOT1_RXN3: CN2.A30 GF1.A65
PCIE_SLOT1_RXN4: CN2.A36 GF1.A69
PCIE_SLOT1_RXN5: CN2.A40 GF1.A73
PCIE_SLOT1_RXN6: CN2.A44 GF1.A77
PCIE_SLOT1_RXN7: CN2.A48 GF1.A81
PCIE_SLOT1_RXN8: CN2.A53 GF1.A86
PCIE_SLOT1_RXN9: CN2.A57 GF1.A90
PCIE_SLOT1_RXN10: CN2.A61 GF1.A94
PCIE_SLOT1_RXN11: CN2.A65 GF1.A98
PCIE_SLOT1_RXN12: CN2.A69 GF1.A102
PCIE_SLOT1_RXN13: CN2.A73 GF1.A106
PCIE_SLOT1_RXN14: CN2.A77 GF1.A110
PCIE_SLOT1_RXN15: CN2.A81 GF1.A114
PCIE_SLOT1_RXP0: CN2.A16 GF1.A52
PCIE_SLOT1_RXP1: CN2.A21 GF1.A56
PCIE_SLOT1_RXP2: CN2.A25 GF1.A60
PCIE_SLOT1_RXP3: CN2.A29 GF1.A64
PCIE_SLOT1_RXP4: CN2.A35 GF1.A68
PCIE_SLOT1_RXP5: CN2.A39 GF1.A72
PCIE_SLOT1_RXP6: CN2.A43 GF1.A76
PCIE_SLOT1_RXP7: CN2.A47 GF1.A80
PCIE_SLOT1_RXP8: CN2.A52 GF1.A85
PCIE_SLOT1_RXP9: CN2.A56 GF1.A89
PCIE_SLOT1_RXP10: CN2.A60 GF1.A93
PCIE_SLOT1_RXP11: CN2.A64 GF1.A97
PCIE_SLOT1_RXP12: CN2.A68 GF1.A101
PCIE_SLOT1_RXP13: CN2.A72 GF1.A105
PCIE_SLOT1_RXP14: CN2.A76 GF1.A109
PCIE_SLOT1_RXP15: CN2.A80 GF1.A113
PCIE_SLOT1_TXN0: CN2.B15 GF1.B51
PCIE_SLOT1_TXN1: CN2.B20 GF1.B55
PCIE_SLOT1_TXN2: CN2.B24 GF1.B59
PCIE_SLOT1_TXN3: CN2.B28 GF1.B63
PCIE_SLOT1_TXN4: CN2.B34 GF1.B67
PCIE_SLOT1_TXN5: CN2.B38 GF1.B71
PCIE_SLOT1_TXN6: CN2.B42 GF1.B75
PCIE_SLOT1_TXN7: CN2.B46 GF1.B79
PCIE_SLOT1_TXN8: CN2.B51 GF1.B84
PCIE_SLOT1_TXN9: CN2.B55 GF1.B88
PCIE_SLOT1_TXN10: CN2.B59 GF1.B92
PCIE_SLOT1_TXN11: CN2.B63 GF1.B96
PCIE_SLOT1_TXN12: CN2.B67 GF1.B100
PCIE_SLOT1_TXN13: CN2.B71 GF1.B104
PCIE_SLOT1_TXN14: CN2.B75 GF1.B108
PCIE_SLOT1_TXN15: CN2.B79 GF1.B112
PCIE_SLOT1_TXP0: CN2.B14 GF1.B50
PCIE_SLOT1_TXP1: CN2.B19 GF1.B54
PCIE_SLOT1_TXP2: CN2.B23 GF1.B58
PCIE_SLOT1_TXP3: CN2.B27 GF1.B62
PCIE_SLOT1_TXP4: CN2.B33 GF1.B66
PCIE_SLOT1_TXP5: CN2.B37 GF1.B70
PCIE_SLOT1_TXP6: CN2.B41 GF1.B74
PCIE_SLOT1_TXP7: CN2.B45 GF1.B78
PCIE_SLOT1_TXP8: CN2.B50 GF1.B83
PCIE_SLOT1_TXP9: CN2.B54 GF1.B87
PCIE_SLOT1_TXP10: CN2.B58 GF1.B91
PCIE_SLOT1_TXP11: CN2.B62 GF1.B95
PCIE_SLOT1_TXP12: CN2.B66 GF1.B99
PCIE_SLOT1_TXP13: CN2.B70 GF1.B103
PCIE_SLOT1_TXP14: CN2.B74 GF1.B107
PCIE_SLOT1_TXP15: CN2.B78 GF1.B111
PCIE_SMCLK: GF1.B5 U10.1
PCIE_SMCLK0: R14.2 RE1.2 U10.5
PCIE_SMCLK1: R16.2 RE10.2 U10.8
PCIE_SMDAT: GF1.B6 U10.2
PCIE_SMDAT0: R13.2 RE7.2 U10.4
PCIE_SMDAT1: R15.2 RE9.2 U10.7
PCIE_WAKE_N: CN1.B11 CN2.B11 GF1.B11
PERST_N: CN1.A11 CN2.A11 R19.1 U9.4
PERST_N_1: R6.1 U8.4
PERST_N_1_R: R6.2 U9.2
PERST_O_1_R: R3.2 R17.2 U8.1
PERST_O_2_R: R4.2 R20.2 U9.1
RESET_IN: C19.1 R1.2 R2.1 U1.3
RESET_O_1: R3.1 U1.2
RESET_O_2: R4.1 U2.2
RESET_P3V3_IN: C23.1 R5.1 U2.3
RSVD0: GF1.B30 TP6.1
RSVD1: GF1.A19 TP7.1
S0_PCIE_SMCLK: CN1.B5 RE1.1
S0_PCIE_SMDAT: CN1.B6 RE7.1
S0_SMB_ALERT_B12_N: CN1.B12 RE4.1
S0_SMB_CLK_A32: CN1.A32 RE2.2
S0_SMB_DAT_A33: CN1.A33 RE3.2
S1_PCIE_SMCLK: CN2.B5 RE10.1
S1_PCIE_SMDAT: CN2.B6 RE9.1
S1_SMB_ALERT_B12_N: CN2.B12 RE8.1
S1_SMB_CLK_A32: CN2.A32 RE5.2
S1_SMB_DAT_A33: CN2.A33 RE6.2
SLOT0_CONFIG: GF1.A50 R33.1
SLOT0_ID_0: CN1.A19 R7.1
SLOT0_ID_1: CN1.B30 R8.2
SLOT1_CONFIG: GF1.A83 R35.1
SLOT1_ID_0: CN2.A19 R9.2
SLOT1_ID_1: CN2.B30 R10.2

Pads without a net: CN1 A5 A6 A7 A8 B9; CN2 A5 A6 A7 A8 A50 B9 B82

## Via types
v1: diameter 0.559, hole 0.305, TOP to BOTTOM, 210 vias
v2: diameter 0.711, hole 0.356, TOP to BOTTOM, 21 vias
v3: diameter 0.711, hole 0.406, TOP to BOTTOM, 29 vias

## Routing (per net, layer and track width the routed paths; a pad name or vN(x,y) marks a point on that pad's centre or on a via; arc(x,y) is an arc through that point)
GND: length 404.8
  TOP w0.381: U8.3 37.26,64.71 v1(37.28,64.73) ; U10.6 v1(32.2,42.59) ; U9.3 v1(37.49,59.63) ; v1(27.6,60.78) 27.01,60.78 26.62,60.39 C23.2
  TOP w0.508: R2.2 C19.2 25.28,68.41 25.29,68.41 v1(25.29,68.45) ; GF1.B109 121.65,6.39 v1(121.15,6.89) ; v1(52.81,48.28) 52.44,47.91 R8.1 ; v1(111.17,6.89) 110.65,6.37 GF1.B98 ; v1(41.09,6.89) 41.65,6.33 GF1.B29 ; GF1.B44 56.65,6.39 v1(57.14,6.89) ; GF1.B93 105.65,6.4 105.63,6.4 v1(105.15,6.89) ; GF1.B32 44.65,6.32 v1(44.09,6.89) ; v1(78.1,6.89) 77.65,6.44 GF1.B65 ; v1(35.75,44.04) 35.79,44.04 36.23,43.6 C24.1 ; v1(72.13,6.89) 72.65,6.36 GF1.B60 ; v1(68.22,6.89) 68.65,6.45 GF1.B56 ; v1(35.2,6.89) 34.65,6.34 GF1.B22 ; GF1.B89 101.65,6.32 v1(101.08,6.89) ; GF1.B94 106.65,6.42 v1(107.13,6.9) ; GF1.B13 v1(25.65,7.07) ; v1(53.1,6.89) 53.1,6.85 52.65,6.4 GF1.B40 ; v1(17.39,6.95) 17.65,6.69 GF1.B7 ; GF1.B77 89.65,6.45 v1(90.09,6.89) ; GF1.B43 55.65,6.32 v1(55.08,6.89) ; GF1.B26 38.65,6.45 v1(39.08,6.89) ; v1(84.17,6.89) 84.65,6.4 GF1.B72 ; v1(123.08,6.89) 122.65,6.46 GF1.B110 ; GF1.B36 48.65,6.24 v1(49.29,6.89) ; v1(56.1,66.77) 55.92,66.95 R10.1 ; GF1.B101 113.65,6.36 v1(113.12,6.89) ; v1(71.47,42.03) 71.07,41.63 R33.2 ; GF1.B21 33.65,6.37 v1(33.14,6.89) ; v1(103.17,6.89) 102.65,6.37 GF1.B90 ; v1(97.15,6.89) 97.65,6.38 GF1.B85 ; GF1.B18 30.65,6.4 v1(31.13,6.89) ; v1(27.6,60.78) 27.61,60.77 U2.1 ; v1(70.15,6.89) 69.65,6.39 GF1.B57 ; v1(51.12,6.89) 51.65,6.36 GF1.B39 ; v1(41.64,59.56) R7.2 ; v1(94.15,6.89) 94.19,6.89 94.65,6.43 GF1.B82 ; GF1.B73 85.65,6.39 v1(86.15,6.89) ; v1(47.13,6.89) 47.65,6.37 GF1.B35 ; GF1.B16 28.65,6.45 v1(28.21,6.89) ; v1(29.93,60.91) 30.23,61.21 C22.2 ; GF1.B113 125.65,6.4 v1(125.17,6.89) ; GF1.B97 109.65,6.45 v1(109.21,6.89) ; v1(66.08,6.89) 65.65,6.45 GF1.B53 ; v1(74.11,6.89) 73.65,6.43 GF1.B61 ; v1(80.15,6.89) 80.65,6.39 GF1.B68 ; v1(88.16,6.89) 88.65,6.39 GF1.B76 ; GF1.B86 98.65,6.46 v1(99.08,6.89) ; v1(115.05,6.89) 114.65,6.48 GF1.B102 ; GF1.B25 37.65,6.31 v1(37.08,6.89) ; v1(15.69,6.9) 14.65,5.86 GF1.B4 ; GF1.B69 81.65,6.44 82.09,6.89 v1(82.11,6.89) ; v1(64.13,6.89) 64.65,6.36 GF1.B52 ; v1(59.15,6.89) 59.65,6.38 GF1.B47 ; GF1.B49 61.65,6.18 v1(62.36,6.89) ; v1(90.16,42.44) 90.34,42.25 R35.2 ; GF1.B64 76.65,6.39 v1(76.14,6.9) ; C18.2 v1(31.69,67.89) 31.34,67.54 C17.2 31.06,66.22 C20.2 ; C21.2 v3(22.06,65.91) ; v1(92.04,6.89) 92.65,6.28 GF1.B80 ; GF1.B105 117.65,6.41 117.63,6.41 v1(117.16,6.89) ; GF1.B106 118.65,6.39 v1(119.14,6.89)
  TOP w1.016: 128.33,67.96 H1.1 ; H1.1 133.3,72.93 ; H1.1 133.3,62.99 ; H2.1 10.97,62.96 ; H2.1 6,57.99 ; H2.1 6,67.93 ; TC4.2 v3(17.53,43.14)
  BOTTOM w0.508: v1(105.15,6.89) 105.15,6.88 104.65,6.38 GF1.A92 ; v1(88.16,6.89) 87.65,6.38 GF1.A75 ; v1(82.11,6.89) 82.65,6.35 GF1.A70 ; v1(37.08,6.89) 36.65,6.46 GF1.A24 ; GF1.A74 86.65,6.38 v1(86.15,6.89) ; v1(68.22,6.89) 67.65,6.32 GF1.A55 ; GF1.A103 115.65,6.29 v1(115.05,6.89) ; GF1.A100 112.65,6.41 v1(113.12,6.89) ; GF1.A42 54.65,6.45 v1(55.08,6.89) ; GF1.A71 83.65,6.44 84.09,6.89 v1(84.17,6.89) ; GF1.A84 96.65,6.39 v1(97.15,6.89) ; GF1.A49 61.65,6.18 v1(62.36,6.89) ; v1(92.04,6.89) 91.65,6.5 GF1.A79 ; GF1.A67 79.65,6.38 v1(80.15,6.89) ; GF1.A38 50.65,6.41 51.12,6.88 v1(51.12,6.89) ; v1(57.14,6.89) 57.65,6.38 GF1.A45 ; GF1.A37 49.65,6.53 v1(49.29,6.89) ; v1(70.15,6.89) 70.65,6.38 GF1.A58 ; v1(59.15,6.89) 58.65,6.39 GF1.A46 ; v1(111.17,6.89) 111.65,6.4 GF1.A99 ; v1(17.39,6.95) 17.39,6.08 17.65,5.82 GF1.A7 ; v1(35.2,6.89) 35.65,6.43 GF1.A23 ; v1(123.08,6.89) 123.08,6.8 123.65,6.23 GF1.A111 ; v1(99.08,6.89) 99.65,6.31 GF1.A87 ; GF1.A63 75.65,6.41 v1(76.14,6.9) ; v1(72.13,6.89) 71.65,6.41 GF1.A59 ; GF1.A15 27.65,6.34 27.66,6.34 v1(28.21,6.89) ; GF1.A4 14.65,5.86 v1(15.69,6.9) ; v1(25.65,7.07) 25.48,7.07 24.65,6.24 GF1.A12 ; v1(125.17,6.89) 124.65,6.37 GF1.A112 ; v1(64.13,6.89) 64.13,6.85 63.65,6.37 GF1.A51 ; GF1.A41 53.65,6.34 v1(53.1,6.89) ; v1(39.08,6.89) 39.65,6.32 GF1.A27 ; GF1.A62 74.65,6.35 v1(74.11,6.89) ; v1(31.13,6.89) 30.65,6.4 GF1.A18 ; v1(119.14,6.89) 119.65,6.38 GF1.A107 ; GF1.A96 108.65,6.32 v1(109.21,6.89) ; GF1.A108 120.65,6.39 v1(121.15,6.89) ; v1(78.1,6.89) 78.65,6.33 GF1.A66 ; v1(41.09,6.89) 40.65,6.45 GF1.A28 ; GF1.A34 46.65,6.34 47.13,6.83 v1(47.13,6.89) ; GF1.A78 90.65,6.32 v1(90.09,6.89) ; v1(94.15,6.89) 94.19,6.89 94.65,6.43 GF1.A82 ; GF1.A95 107.65,6.38 v1(107.13,6.9) ; v1(117.16,6.89) 116.65,6.39 GF1.A104 ; GF1.A88 100.65,6.45 v1(101.08,6.89) ; v1(66.08,6.89) 66.65,6.32 GF1.A54 ; v1(44.09,6.89) 44.05,6.89 43.65,6.48 GF1.A31 ; v1(103.17,6.89) 103.65,6.4 GF1.A91 ; v1(33.14,6.89) 33.14,6.88 32.65,6.39 GF1.A20
  BOTTOM w0.711: v1(127.21,6.89) 127.65,6.44 GF1.A115
  vias: v1(1.12,77.4) v1(1.12,74.86) v1(1.12,72.32) v1(1.12,69.78) v1(2.39,76.13) v1(2.39,73.59) v1(2.39,71.05) v1(2.39,68.51) v1(3.66,77.4) v1(3.66,74.86) v1(3.66,69.78) v1(4.93,76.13) v1(6.2,77.4) v1(6.2,74.86) v1(6.2,69.78) v1(7.47,76.13) v1(7.47,73.59) v1(7.47,71.05) v1(8.74,77.4) v1(8.74,74.86) v1(8.74,72.32) v1(8.74,69.78) v1(10.01,76.13) v1(10.01,73.59) v1(10.01,71.05) v1(10.01,68.51) v1(11.28,77.4) v1(12.55,76.13) v1(13.82,77.4) v1(15.09,76.13) v1(17.11,30.93) v1(17.11,25.9) v1(17.71,22.71) v1(25.23,37.76) v1(25.23,34.49) v1(25.23,31.23) v1(26.31,45.69) v1(26.61,23.72) v1(27.1,43.61) v1(27.1,42.54) v1(27.8,47.57) v1(28.41,23.77) v1(110.21,74.79) v1(110.21,69.71) v1(110.21,64.63) v1(110.21,59.55) v1(112.75,77.33) v1(112.75,72.25) v1(112.75,67.17) v1(112.75,62.09) v1(112.75,57.01) v1(112.75,51.93) v1(115.29,74.79) v1(115.29,69.71) v1(115.29,64.63) v1(115.29,59.55) v1(115.29,54.47) v1(115.29,49.39) v1(115.29,44.31) v1(117.83,77.33) v1(117.83,72.25) v1(117.83,67.17) v1(117.83,62.09) v1(117.83,57.01) v1(117.83,51.93) v1(117.83,46.85) v1(117.83,41.77) v1(117.83,36.69) v1(120.37,74.79) v1(120.37,69.71) v1(120.37,64.63) v1(120.37,59.55) v1(120.37,54.47) v1(120.37,49.39) v1(120.37,44.31) v1(120.37,39.23) v1(120.37,34.15) v1(122.91,77.33) v1(122.91,72.25) v1(122.91,67.17) v1(122.91,62.09) v1(122.91,57.01) v1(122.91,51.93) v1(122.91,46.85) v1(122.91,41.77) v1(122.91,36.69) v1(125.45,74.79) v1(125.45,69.71) v1(125.45,64.63) v1(125.45,59.55) v1(125.45,54.47) v1(125.45,49.39) v1(125.45,44.31) v1(125.45,39.23) v1(125.45,34.15) v1(127.99,77.33) v1(127.99,72.25) v1(127.99,67.17) v1(127.99,62.09) v1(127.99,57.01) v1(127.99,51.93) v1(127.99,46.85) v1(127.99,41.77) v1(127.99,36.69) v1(130.53,74.79) v1(133.07,77.33) v1(135.61,74.79) v1(138.15,77.33) v2(17.04,54.96) v2(117.69,70.54) v2(120.37,47.15) v3(26.31,65.57) v3(26.31,64.36) v3(27,63.3)
P3V3: length 26.1
  TOP w0.711: GF1.B8 18.65,7.17 v3(18.69,7.21)
  TOP w1.016: 29.09,51.27 CN1.B8 29.09,49.5 ; 29.09,71.59 CN2.B8 29.09,69.82 ; 31.09,57.77 CN1.A10 30.41,56.21 ; 30.09,74.32 CN2.A9 29.41,74.53 ; 30.09,54 CN1.A9 30.09,55.77
  BOTTOM w0.711: 20.59,6.84 20.65,6.78 GF1.A10 ; GF1.A9 19.65,8.07 19.82,8.24
  BOTTOM w1.016: 29.09,71.59 CN2.B8 29.09,69.82 ; 31.09,76.32 CN2.A10 30.41,76.53 ; 30.09,76.09 CN2.A9 30.09,74.32
  vias: v1(27.2,68.68) v1(28.26,68.7) v1(29.33,68.68) v2(20.82,10.66) v3(18.69,12.08) v3(18.69,10.86) v3(18.69,9.65) v3(18.69,8.43) v3(19.91,12.08) v3(22,64.4) v3(22,63.18) v3(23.22,64.4) v3(23.22,63.18)
P3V3_AUX: length 28.8
  TOP w0.381: C24.2 35.88,42.71 35.76,42.59 U10.3
  TOP w0.508: 30.24,36.74 31.09,37.59 35.35,37.59 36.65,38.89 C24.2 37.13,42.71 37.55,43.13 37.55,44.07 37.16,44.46 37.08,44.46 36.48,45.06 R13.1
  TOP w0.711: GF1.B10 20.65,9.17
  TOP w1.016: 31.09,49.5 CN1.B10 ; CN1.B10 31.09,51.27 ; CN1.B10 31.98,50.39 ; 31.77,71.38 CN2.B10 31.98,70.71
  vias: v1(32.6,63.8) v1(33.55,68.8) v1(33.63,64.78) v1(34.43,67.91) v2(29.3,41.29) v3(29.15,39.31) v3(29.35,44.8) v3(29.79,38.18) v3(30.75,47.34) v3(33.16,60.04) v3(34.38,60.04)
P12V: length 39.4
  TOP w0.635: CN1.A3 23.14,54.89
  TOP w0.711: GF1.B1 11.65,7.26 12.15,7.77 v3(12.87,7.77) ; GF1.B3 13.65,6.99 ; GF1.B2 12.65,6.7
  TOP w1.016: 22.2,56.89 CN1.A2 23.09,56 ; CN2.B2 23.09,71.59 ; CN2.B2 22.2,70.71 ; CN2.B2 23.09,69.82 ; 22.09,51.5 CN1.B1 ; CN1.B1 22.09,53.27 ; CN1.B1 21.2,52.39 ; 24.09,51.5 CN1.B3 24.09,53.27 ; 23.09,51.27 CN1.B2 22.2,50.39 ; 24.09,54 CN1.A3 24.09,55.77 ; 22.09,71.82 CN2.B1 ; CN2.B1 21.2,72.71 ; CN2.B1 22.09,73.59 ; 23.41,74.53 CN2.A3 24.09,74.32 ; 24.09,73.59 CN2.B3 24.09,71.82
  BOTTOM w0.711: GF1.A2 12.65,6.5 ; GF1.A3 13.65,6.66
  BOTTOM w1.016: CN2.A2 24.09,76.21 CN2.A3
  vias: v3(12.87,11.42) v3(12.87,10.2) v3(12.87,8.99) v3(15,11.47) v3(15,10.26) v3(15,9.04) v3(15,7.82)
CLK100_PCIE_SLOT0_N: length 68
  BOTTOM w0.178: CN1.A14 37.09,56.88 36.74,56.18 arc(36.73,56.05) 36.82,55.94 37.01,55.84 arc(37.19,55.61) 37.25,55.33 37.25,51.96 38.22,51 38.22,49.78 37.51,49.07 37.28,49.07 35.95,47.73 35.82,46.99 35.28,46.22 34.88,45.65 34.76,45.01 35.09,43.18 34.75,41.29 34.22,40.52 34.18,40.48 32.94,39.23 32.94,35.98 32.18,35.22 31.56,35.22 25.28,28.94 18.65,28.94 15.91,26.2 15.91,21.29 16.78,20.42 16.78,6.58 16.65,6.44 GF1.A6
CLK100_PCIE_SLOT0_P: length 68
  BOTTOM w0.178: CN1.A13 36.38,55.46 36.44,55.59 arc(36.55,55.68) 36.68,55.67 36.84,55.59 arc(36.92,55.47) 36.95,55.33 36.95,51.83 37.91,50.87 37.91,49.9 37.38,49.37 37.16,49.37 35.66,47.88 35.58,47.41 35.53,47.11 35.03,46.4 34.59,45.77 34.45,45.01 34.78,43.18 34.46,41.41 33.95,40.68 32.63,39.36 32.63,36.11 32.05,35.53 31.44,35.53 25.15,29.24 18.52,29.24 15.6,26.32 15.6,21.16 16.48,20.29 16.48,6.7 16.35,6.57 16.35,6.42 16.1,6.17 15.99,6.17 15.65,5.82 GF1.A5
CLK100_PCIE_SLOT1_N: length 85.8
  BOTTOM w0.178: GF1.A33 45.65,5.9 45.33,6.22 45.33,6.63 48.57,11.26 50.98,24.89 51.03,25.2 54.8,46.59 54.8,46.63 54.8,46.97 54.25,50.14 54.25,50.77 arc(54.27,50.91) 54.35,51.03 54.97,51.64 arc(55.17,51.94) 55.24,52.29 55.24,55.29 arc(55.19,55.5) 55.08,55.68 54.46,56.3 arc(54.45,56.31) 54.44,56.31 arc(54.3,56.54) 54.25,56.81 54.25,57.19 arc(53.97,57.87) 53.29,58.15 52.98,58.15 52.32,58.24 47.96,58.78 46.1,60.08 41.26,67 38.5,69.76 38.24,70.18 38.24,71 arc(38.19,71.26) 38.05,71.47 37.44,72.08 arc(37.29,72.3) 37.24,72.56 37.24,75.55 arc(37.17,75.89) 36.98,76.18 36.82,76.26 36.82,76.26 arc(36.73,76.36) 36.74,76.5 CN2.A14
CLK100_PCIE_SLOT1_P: length 85.8
  BOTTOM w0.178: GF1.A32 44.65,5.87 45.03,6.24 45.03,6.72 48.28,11.37 48.95,15.16 48.85,15.3 48.94,15.82 49.09,15.93 49.18,16.45 49.08,16.6 49.17,17.12 49.31,17.22 49.41,17.75 49.31,17.89 49.4,18.42 49.54,18.52 50.67,24.89 50.72,25.2 54.5,46.61 54.49,46.97 53.94,50.11 53.94,50.77 arc(53.99,51.03) 54.14,51.24 54.75,51.86 arc(54.89,52.06) 54.93,52.29 54.93,55.29 arc(54.91,55.38) 54.86,55.46 54.22,56.1 54.22,56.11 arc(54.01,56.43) 53.94,56.81 53.94,57.19 arc(53.75,57.66) 53.29,57.85 52.98,57.85 arc(52.97,57.85) 52.96,57.85 52.28,57.93 47.85,58.49 46.86,59.18 45.88,59.86 41.02,66.8 38.26,69.57 37.94,70.09 37.94,70.68 37.94,71 arc(37.91,71.14) 37.83,71.26 37.22,71.87 arc(37.01,72.19) 36.93,72.56 36.93,75.55 arc(36.9,75.75) 36.79,75.93 36.68,75.99 36.68,75.99 arc(36.55,76) 36.44,75.91 CN2.A13
CLK100_PCIE_SLOT_N: length 8.6
  BOTTOM w0.178: TP2.1 27.56,10.55 27.56,10.14 26.3,6.43 26.3,6.1 26.65,5.76 GF1.A14
CLK100_PCIE_SLOT_P: length 8.5
  BOTTOM w0.178: GF1.A13 25.65,5.79 26,6.14 26,6.48 27.26,10.19 27.26,10.57 TP1.1
LAN_SMB_ALERT_N: length 71.4
  TOP w0.178: v1(39.42,64.34) 38.54,64.34 RE8.2 ; GF1.B12 24.65,5.67 24.97,5.99 24.97,9.11 32.33,16.47 32.33,33.46 37.55,38.68 37.55,42.06 38.32,42.83 38.32,45.74 37.84,46.22 37.6,46.22 36.47,47.34 RE4.2 36.18,48.53 35.74,48.97 v1(35.74,49.12)
  BOTTOM w0.178: v1(39.42,64.34) v2(39.42,62.99) 39.42,59.43 37.98,57.99 37.06,57.99 36.26,57.19 36.26,56.42 35.26,55.42 35.26,54.42 35.33,54.35 35.33,52.95 35.2,52.83 35.2,51.47 36.11,50.57 36.11,49.95 35.74,49.59 v1(35.74,49.12)
LAN_SMB_CLK: length 73.4
  TOP w0.178: v1(27.93,24.68) 27.72,24.47 27.72,16.11 24.25,12.64 22.5,12.64 19.65,9.79 GF1.B9 ; RE5.1 40.5,62.58 v1(40.5,61.82) 40.56,61.76 40.56,61.73 41.18,61.11 42.31,61.11 RE2.1 ; v1(39.19,58.1) 39.07,58.1 38.14,57.17 38.14,56.51 37.05,55.42 37.05,52.22 36.09,51.26 36.09,49.59 36.84,48.84 36.84,48.32 38,47.15 v1(38,47.1)
  BOTTOM w0.178: v1(40.5,61.82) 40.5,61.82 40.5,59.41 v1(39.19,58.1) ; v1(27.93,24.68) 27.93,24.86 35.54,32.47 35.7,33.26 35.75,33.48 37.45,35.18 v2(37.45,43.29) 36.92,43.81 36.92,45.57 37.61,46.26 37.61,46.62 37.61,46.77 37.93,47.1 v1(38,47.1)
LAN_SMB_DAT: length 76.1
  TOP w0.178: v1(23.87,13.35) 24.35,13.35 27.29,16.29 27.29,24.31 v1(26.92,24.68) ; v1(38.35,53.69) 39.08,54.43 39.08,55.37 40.07,56.36 40.07,57.3 v1(40.89,58.12) ; RE6.1 41.42,62.81 v1(41.42,61.82) 41.7,61.54 42.14,61.54 RE3.1
  BOTTOM w0.178: v1(26.92,24.68) 27.64,25.41 27.87,25.41 28.19,25.73 31.4,28.94 35.14,32.68 35.27,33.31 35.27,33.31 35.45,34.15 36.09,34.79 v2(36.09,41) 36.26,41.16 36.26,44.42 36.49,44.65 36.49,45.75 37.18,46.44 37.18,47.39 37.76,47.97 37.96,47.97 38.26,48.28 38.46,48.28 40.05,49.87 40.05,50.79 39.44,51.4 39.11,51.73 39.11,52.93 v1(38.35,53.69) ; v1(40.89,58.12) 40.94,58.17 40.94,61.3 41.18,61.54 41.18,61.58 v1(41.42,61.82) ; GF1.A8 18.65,5.87 17.91,6.61 17.91,12.36 18.9,13.35 v1(23.87,13.35)
MB_PD_SLOT_PRSNT: length 79
  BOTTOM w0.178: CN1.A1 22.09,54.88 ; 22.09,54.88 11.6,44.39 11.6,25.37 12.17,24.8 12.17,11.94 11.85,11.63 11.85,5.9 11.65,5.7 GF1.A1 ; 22.09,54.88 18.43,58.54 18.43,71.55 CN2.A1
PCH_PLTRST_N: length 72.2
  TOP w0.178: v1(35.03,62.59) 35.43,62.99 R19.2 35.93,63.57 35.73,63.76 U8.2 ; v1(34.94,58.26) 34.94,57.93 34.18,57.17 34.18,55.61 35.53,54.26 35.53,52.97 34.12,51.55 34.12,48.5 34.41,48.21 34.41,47.12 35.36,46.17 36.57,46.17 37.44,45.31 v1(37.61,45.31)
  BOTTOM w0.178: v1(34.94,58.26) 35.03,58.35 v1(35.03,62.59) ; GF1.A11 21.65,5.74 21.34,6.05 21.34,8.42 22.71,9.79 23.15,9.79 29.01,15.65 32.69,23.8 37.11,33.62 38.13,34.64 38.39,36.15 v2(38.39,36.63) 38.39,40.44 39.1,42.82 39.1,43.63 37.61,45.11 v1(37.61,45.31)
PCIE_CPRSNT_N: length 7
  TOP w0.178: GF1.B114 126.65,6.46 124.53,8.57 TP3.1
PCIE_SLOT0_CPRSNT1_N: length 66.7
  TOP w0.178: CN1.B31 54.09,53.16 53.71,53.54 41.24,53.54 CN1.B17 40.09,51.18 41.23,44.7 38.87,31.31 38.82,31.01 36.47,17.67 29.65,7.93 GF1.B17
PCIE_SLOT0_CPRSNT2_N: length 70.1
  TOP w0.178: GF1.B31 43.65,6.4 43.59,6.46 43.59,8.41 47.57,31.01 47.63,31.31 47.84,32.53 49.36,41.14 49.41,41.4 54.12,48.13 54.12,51.02 55.14,52.04 55.14,53.18 55.64,53.69 68.47,53.69 69.08,53.08 69.08,51.94 69.77,51.25 70.22,51.25 CN1.B48
PCIE_SLOT0_RXN0: length 58.2
  BOTTOM w0.178: CN1.A17 39.74,55.59 arc(39.63,55.68) 39.5,55.67 39.39,55.61 39.39,55.61 39.26,55.26 39.26,54.52 arc(39.48,53.99) 40.01,53.77 40.18,53.77 arc(40.93,53.46) 41.24,52.71 41.24,52.29 arc(41.31,51.98) 41.48,51.72 41.94,51.26 arc(42.16,50.94) 42.23,50.57 42.23,49.87 37.03,20.4 34.57,16.89 34.6,16.71 34.3,16.28 34.12,16.25 33.82,15.81 33.85,15.64 33.54,15.2 33.37,15.17 33.06,14.73 33.09,14.56 32.79,14.12 32.61,14.09 31.8,12.92 30.61,11.22 30.04,10.42 29.87,10.17 29.78,9.65 29.88,9.5 29.78,8.98 29.64,8.88 29.55,8.35 29.36,7.28 29.36,6.39 29.65,6.1 GF1.A17
PCIE_SLOT0_RXN1: length 55.7
  BOTTOM w0.178: CN1.A22 44.74,56.18 arc(44.73,56.05) 44.82,55.94 45.01,55.84 arc(45.17,55.64) 45.23,55.39 45.23,52.22 arc(45.16,51.89) 44.98,51.61 44.56,51.19 arc(44.32,50.84) 44.24,50.42 44.24,49.88 37.46,11.47 34.33,6.99 34.33,6.26 34.65,5.93 GF1.A22
PCIE_SLOT0_RXN2: length 55.5
  BOTTOM w0.178: GF1.A26 38.65,5.96 38.32,6.29 38.32,6.97 39.94,9.28 41.12,15.01 41.12,15.01 48.25,49.49 48.25,50.6 arc(48.29,50.8) 48.4,50.97 48.94,51.5 arc(49.16,51.84) 49.24,52.24 49.24,55.22 arc(49.17,55.57) 48.98,55.86 48.82,55.94 48.82,55.94 arc(48.73,56.04) 48.74,56.18 CN1.A26
PCIE_SLOT0_RXN3: length 55.7
  BOTTOM w0.178: GF1.A30 42.65,6.05 42.31,6.39 42.31,7.04 45.39,11.44 45.39,11.44 46.23,16.18 47.76,24.89 47.82,25.2 52.24,50.24 arc(52.24,50.26) 52.24,50.29 52.24,50.49 arc(52.29,50.72) 52.42,50.92 52.58,51.09 52.86,51.37 52.95,51.45 arc(53.18,51.79) 53.26,52.19 53.26,55.19 arc(53.18,55.55) 52.98,55.86 52.82,55.94 52.82,55.94 arc(52.73,56.04) 52.74,56.18 CN1.A30
PCIE_SLOT0_RXN4: length 55.8
  BOTTOM w0.178: CN1.A36 58.74,56.18 arc(58.73,56.04) 58.82,55.94 58.82,55.94 58.98,55.86 arc(59.18,55.56) 59.25,55.2 59.25,52.32 arc(59.16,51.87) 58.91,51.49 58.41,51 arc(58.28,50.8) 58.23,50.57 58.23,49.52 53.94,25.2 53.89,24.89 52.61,17.61 52.54,17.24 52.46,16.79 52.38,16.34 51.5,11.32 50.45,9.82 49.12,7.93 48.33,6.79 48.33,6.26 48.65,5.93 GF1.A36
PCIE_SLOT0_RXN5: length 55.8
  BOTTOM w0.178: GF1.A40 52.65,5.93 52.33,6.25 52.33,6.77 55.34,11.07 55.44,11.17 55.58,11.97 55.65,12.36 56.29,16.02 57.86,24.89 57.91,25.2 58.61,29.15 62.08,48.84 62.26,49.87 62.25,49.9 62.25,50.59 arc(62.29,50.8) 62.41,50.98 62.88,51.45 arc(63.14,51.85) 63.24,52.32 63.24,55.37 arc(63.19,55.6) 63.06,55.81 arc(63.04,55.82) 63.01,55.84 62.82,55.94 arc(62.73,56.05) 62.74,56.18 CN1.A40
PCIE_SLOT0_RXN6: length 55.7
  BOTTOM w0.178: CN1.A44 66.74,56.18 arc(66.73,56.04) 66.82,55.94 66.98,55.86 arc(67.18,55.56) 67.25,55.2 67.25,52.19 arc(67.18,51.84) 66.98,51.54 66.43,50.98 arc(66.28,50.77) 66.23,50.52 66.23,49.67 61.88,25.2 61.83,24.89 59.38,11.12 56.33,6.77 56.33,6.25 56.65,5.93 GF1.A44
PCIE_SLOT0_RXN7: length 55.8
  BOTTOM w0.178: GF1.A48 60.65,5.93 60.32,6.26 60.32,6.79 63.44,11.24 63.64,12.41 64.41,16.75 64.53,17.43 64.53,17.43 65.84,24.89 65.9,25.2 68.7,41.08 70.07,48.84 70.27,49.95 70.25,49.98 70.25,50.53 arc(70.31,50.82) 70.47,51.07 70.6,51.2 71.08,51.68 arc(71.2,51.85) 71.24,52.06 71.24,55.23 arc(71.17,55.57) 70.98,55.86 70.82,55.94 arc(70.73,56.04) 70.74,56.18 CN1.A48
PCIE_SLOT0_RXP0: length 58.1
  BOTTOM w0.178: CN1.A16 39.44,56.18 arc(39.45,56.04) 39.36,55.94 39.2,55.86 39.13,55.79 38.96,55.32 38.96,54.52 arc(39.26,53.78) 40.01,53.47 40.18,53.47 arc(40.72,53.25) 40.94,52.71 40.94,52.29 arc(41.02,51.87) 41.27,51.51 41.5,51.27 41.73,51.04 arc(41.88,50.82) 41.93,50.56 41.93,49.9 36.75,20.52 34.04,16.66 30.36,11.4 29.58,10.29 29.05,7.31 29.05,6.45 28.65,6.05 GF1.A16
PCIE_SLOT0_RXP1: length 55.7
  BOTTOM w0.178: GF1.A21 33.65,5.93 34.02,6.31 34.02,7.09 37.17,11.59 37.81,15.2 37.71,15.35 37.8,15.87 37.95,15.97 38.04,16.5 37.94,16.64 38.03,17.17 38.18,17.27 38.27,17.79 38.17,17.94 38.26,18.46 38.4,18.56 43.93,49.91 43.93,50.42 arc(44.04,50.95) 44.34,51.4 44.76,51.83 arc(44.88,52.01) 44.92,52.22 44.92,55.39 arc(44.9,55.5) 44.84,55.59 44.68,55.67 arc(44.55,55.68) 44.44,55.59 CN1.A21
PCIE_SLOT0_RXP2: length 55.5
  BOTTOM w0.178: CN1.A25 48.44,55.59 arc(48.55,55.68) 48.68,55.67 48.68,55.67 48.79,55.61 arc(48.9,55.43) 48.94,55.22 48.94,52.24 arc(48.88,51.96) 48.72,51.72 48.19,51.19 arc(48.01,50.92) 47.95,50.6 47.95,49.52 40.85,15.19 40.7,15.1 40.6,14.58 40.69,14.43 40.58,13.91 40.44,13.81 40.33,13.29 40.43,13.14 40.32,12.62 40.17,12.52 40.06,12 40.16,11.85 39.65,9.4 38.02,7.06 38.02,6.3 37.65,5.93 GF1.A25
PCIE_SLOT0_RXP3: length 55.7
  BOTTOM w0.178: GF1.A29 41.65,6.04 42,6.39 42,7.13 45.1,11.56 45.93,16.23 46.18,17.68 46.08,17.82 46.17,18.35 46.32,18.45 46.41,18.97 46.31,19.12 46.4,19.64 46.55,19.74 46.64,20.27 46.54,20.41 46.63,20.94 46.77,21.04 47.45,24.89 47.51,25.2 51.93,50.29 arc(51.94,50.3) 51.94,50.3 51.94,50.49 arc(52,50.84) 52.2,51.14 52.37,51.3 52.65,51.58 52.73,51.67 arc(52.89,51.91) 52.95,52.19 52.95,55.19 arc(52.91,55.41) 52.79,55.61 52.68,55.67 52.68,55.67 arc(52.55,55.68) 52.44,55.59 CN1.A29
PCIE_SLOT0_RXP4: length 55.7
  BOTTOM w0.178: GF1.A35 47.65,5.89 48.02,6.27 48.02,6.88 48.87,8.1 50.2,9.99 50.78,10.83 51.21,11.43 51.3,11.96 51.2,12.1 51.29,12.63 51.44,12.73 51.53,13.26 51.43,13.4 51.52,13.93 51.67,14.03 51.76,14.55 51.66,14.7 51.75,15.22 51.89,15.32 52.08,16.39 52.24,17.29 52.31,17.66 53.58,24.89 53.64,25.2 57.93,49.55 57.93,50.57 arc(58,50.92) 58.2,51.21 58.69,51.71 arc(58.88,51.99) 58.95,52.32 58.95,55.2 arc(58.91,55.42) 58.79,55.61 58.68,55.67 58.68,55.67 arc(58.55,55.68) 58.44,55.59 CN1.A35
PCIE_SLOT0_RXP5: length 55.7
  BOTTOM w0.178: CN1.A39 62.44,55.59 arc(62.55,55.68) 62.68,55.67 62.84,55.59 arc(62.91,55.49) 62.93,55.37 62.93,52.32 arc(62.86,51.97) 62.66,51.67 62.2,51.2 arc(62.01,50.92) 61.94,50.59 61.94,49.8 61.78,48.89 58.31,29.2 57.6,25.2 57.55,24.89 56.68,19.96 56.54,19.86 56.44,19.34 56.54,19.19 56.45,18.67 56.31,18.57 56.21,18.04 56.32,17.9 56.22,17.37 56.08,17.27 55.99,16.75 56.09,16.6 55.99,16.08 55.35,12.41 55.28,12.02 55.16,11.34 52.02,6.86 52.02,6.28 51.65,5.91 GF1.A39
PCIE_SLOT0_RXP6: length 55.7
  BOTTOM w0.178: GF1.A43 55.65,5.89 56.02,6.27 56.02,6.87 59.09,11.24 60.06,16.69 60.34,18.28 60.24,18.43 60.33,18.95 60.48,19.05 60.57,19.58 60.47,19.72 60.56,20.25 60.71,20.35 60.8,20.87 60.7,21.02 60.79,21.54 60.94,21.65 61.52,24.89 61.57,25.2 65.93,49.7 65.93,50.52 arc(66,50.89) 66.21,51.2 66.77,51.76 arc(66.9,51.96) 66.95,52.19 66.95,55.2 66.95,55.2 arc(66.91,55.42) 66.79,55.61 66.68,55.67 66.68,55.67 arc(66.55,55.68) 66.44,55.59 CN1.A43
PCIE_SLOT0_RXP7: length 55.7
  BOTTOM w0.178: GF1.A47 59.65,5.93 60.02,6.3 60.02,6.89 63.15,11.36 63.34,12.47 63.34,12.47 64.11,16.8 64.24,17.55 64.4,18.43 64.29,18.58 64.39,19.1 64.53,19.2 64.62,19.73 64.52,19.87 64.62,20.4 64.76,20.5 64.85,21.03 64.75,21.17 64.84,21.69 64.99,21.8 65.53,24.89 65.59,25.2 68.4,41.13 69.77,48.89 69.94,49.88 69.94,50.53 arc(70.02,50.94) 70.25,51.28 70.39,51.42 70.87,51.89 arc(70.92,51.97) 70.93,52.06 70.93,55.23 arc(70.9,55.43) 70.79,55.61 70.68,55.67 70.68,55.67 arc(70.55,55.68) 70.44,55.59 CN1.A47
PCIE_SLOT0_TXN0: length 52.5
  TOP w0.178: CN1.B15 37.74,51.68 arc(37.72,51.57) 37.77,51.47 37.8,51.47 38.22,51.07 38.22,50.36 38.38,49.47 39.56,47.78 40.11,44.67 37.75,31.31 37.7,31.01 35.45,18.28 27.35,6.71 27.35,6.19 27.65,5.89 GF1.B15
PCIE_SLOT0_TXN1: length 51.2
  TOP w0.178: GF1.B20 32.65,5.92 32.29,6.28 32.29,8.18 33.87,10.44 34.04,10.47 34.35,10.91 34.32,11.08 34.63,11.52 34.8,11.55 35.11,11.98 35.07,12.16 35.38,12.59 35.55,12.62 35.86,13.06 35.83,13.24 37.29,15.33 37.53,15.67 40.24,31.01 40.29,31.31 42.67,44.82 42.23,47.33 42.23,50.69 arc(42.27,50.92) 42.39,51.11 42.5,51.17 arc(42.63,51.18) 42.74,51.09 CN1.B20
PCIE_SLOT0_TXN2: length 50.6
  TOP w0.178: GF1.B24 36.65,5.81 36.27,6.19 36.27,6.53 36.37,7.12 36.7,9 37.15,9.64 37.32,9.67 37.63,10.1 37.6,10.28 37.9,10.71 38.08,10.74 38.38,11.18 38.35,11.35 38.66,11.79 38.83,11.82 39.14,12.26 39.11,12.43 39.84,13.48 42.93,31.01 42.99,31.31 46.22,49.63 46.24,50.66 46.44,51.14 46.5,51.17 arc(46.63,51.18) 46.74,51.09 CN1.B24
PCIE_SLOT0_TXN3: length 50.7
  TOP w0.178: CN1.B28 50.74,51.09 arc(50.63,51.18) 50.5,51.17 50.39,51.11 arc(50.27,50.92) 50.23,50.7 50.23,50.7 50.23,49.85 50,48.54 46.58,43.65 44.41,31.31 44.35,31.01 41.06,12.36 41.17,12.21 41.07,11.67 40.93,11.57 40.83,11.03 40.93,10.89 40.84,10.35 40.69,10.25 40.6,9.71 40.7,9.57 40.6,9.03 40.46,8.93 40.31,8.08 40.31,7.45 40.38,7.38 40.38,6.84 40.31,6.78 40.31,6.31 40.65,5.97 GF1.B28
PCIE_SLOT0_TXN4: length 50.7
  TOP w0.178: CN1.B34 56.74,51.09 arc(56.63,51.18) 56.5,51.17 56.5,51.17 56.39,51.11 arc(56.29,50.94) 56.25,50.74 56.25,49.88 55.53,45.79 52.03,40.79 47.21,13.45 47.31,13.31 47.22,12.78 47.08,12.68 46.98,12.15 47.08,12.01 46.99,11.49 46.85,11.38 46.75,10.86 46.86,10.71 46.76,10.19 46.62,10.09 46.29,8.23 46.29,6.29 46.65,5.93 GF1.B34
PCIE_SLOT0_TXN5: length 50.6
  TOP w0.178: CN1.B38 60.74,51.09 arc(60.63,51.18) 60.5,51.17 60.5,51.17 60.39,51.11 arc(60.28,50.93) 60.24,50.71 60.24,49.9 59.9,47.98 56.73,43.45 51.06,11.28 51.16,11.13 51.06,10.61 50.92,10.51 50.83,9.98 50.93,9.84 50.84,9.31 50.69,9.21 50.6,8.69 50.7,8.54 50.61,8.02 50.46,7.92 50.28,6.89 50.28,6.3 50.65,5.93 GF1.B38
PCIE_SLOT0_TXN6: length 50.5
  TOP w0.178: CN1.B42 64.74,51.09 arc(64.63,51.18) 64.5,51.17 64.44,51.14 64.25,50.69 64.25,50.14 64,48.72 61.69,45.41 61.68,45.41 58.99,31.31 58.93,31.01 55.96,15.44 56.06,15.29 55.95,14.75 55.81,14.66 55.7,14.12 55.8,13.97 55.7,13.44 55.56,13.34 55.45,12.8 55.55,12.66 55.45,12.12 55.3,12.02 55.28,11.88 54.84,9.49 54.81,9.32 54.85,9.11 54.77,8.67 54.67,8.52 54.58,7.99 54.32,6.54 54.32,6.27 54.65,5.93 GF1.B42
PCIE_SLOT0_TXN7: length 50.6
  TOP w0.178: CN1.B46 68.74,51.09 arc(68.63,51.18) 68.5,51.17 68.5,51.17 68.39,51.11 arc(68.3,50.96) 68.27,50.78 68.27,49.66 65.59,45.84 62.89,31.31 62.83,31.01 59.6,13.69 59.7,13.55 59.6,13.01 59.46,12.91 59.36,12.37 59.46,12.23 59.36,11.71 59.21,11.61 59.12,11.08 59.22,10.94 59.12,10.41 58.97,10.31 58.73,9.02 58.29,6.66 58.29,6.26 58.65,5.9 GF1.B46
PCIE_SLOT0_TXP0: length 52.5
  TOP w0.178: CN1.B14 37.44,51.09 arc(37.55,51.18) 37.68,51.17 37.68,51.17 37.91,50.94 37.91,50.34 38.09,49.35 39.27,47.66 39.8,44.67 37.44,31.31 37.39,31.01 35.97,22.97 35.82,22.87 35.73,22.34 35.83,22.2 35.74,21.67 35.6,21.57 35.5,21.04 35.6,20.9 35.51,20.37 35.37,20.27 35.27,19.75 35.38,19.6 35.16,18.4 27.04,6.81 27.04,6.27 26.65,5.87 GF1.B14
PCIE_SLOT0_TXP1: length 51.2
  TOP w0.178: GF1.B19 31.65,5.95 31.99,6.28 31.99,8.28 37.04,15.5 37.25,15.79 39.93,31.01 39.98,31.31 42.37,44.82 41.93,47.31 41.93,50.69 arc(42,51.06) 42.2,51.36 42.36,51.44 arc(42.45,51.54) 42.44,51.68 CN1.B19
PCIE_SLOT0_TXP2: length 50.6
  TOP w0.178: GF1.B23 35.65,5.83 35.96,6.15 35.96,6.56 36.41,9.12 38.87,12.62 38.88,12.63 39.56,13.6 42.62,31.01 42.68,31.31 45.91,49.66 45.94,50.73 46.2,51.36 46.36,51.44 arc(46.45,51.54) 46.44,51.68 CN1.B23
PCIE_SLOT0_TXP3: length 50.7
  TOP w0.178: CN1.B27 50.44,51.68 arc(50.45,51.54) 50.36,51.44 50.2,51.36 arc(50,51.06) 49.93,50.7 49.93,49.88 49.71,48.66 46.29,43.77 44.1,31.31 44.04,31.01 40.01,8.11 40.01,6.29 39.65,5.94 GF1.B27
PCIE_SLOT0_TXP4: length 50.7
  TOP w0.178: GF1.B33 45.65,5.9 45.99,6.24 45.99,8.26 51.74,40.91 55.24,45.9 55.95,49.9 55.95,50.74 arc(56.01,51.08) 56.2,51.36 56.36,51.44 arc(56.45,51.54) 56.44,51.68 CN1.B33
PCIE_SLOT0_TXP5: length 50.7
  TOP w0.178: GF1.B37 49.65,5.94 49.98,6.27 49.98,6.92 50.76,11.33 56.44,43.57 59.61,48.1 59.94,49.93 59.94,50.71 arc(59.94,50.72) 59.94,50.72 arc(60.01,51.07) 60.2,51.36 60.36,51.44 arc(60.45,51.54) 60.44,51.68 CN1.B37
PCIE_SLOT0_TXP6: length 50.5
  TOP w0.178: CN1.B41 64.44,51.68 arc(64.45,51.54) 64.36,51.44 64.2,51.36 63.95,50.75 63.95,50.17 63.71,48.84 61.49,45.67 61.4,45.54 61.39,45.48 58.68,31.31 58.62,31.01 54.98,11.93 54.6,9.84 54.58,9.73 54.5,9.32 54.49,9.24 54.33,8.38 54.27,8.04 54.01,6.57 54.01,6.3 53.65,5.93 GF1.B41
